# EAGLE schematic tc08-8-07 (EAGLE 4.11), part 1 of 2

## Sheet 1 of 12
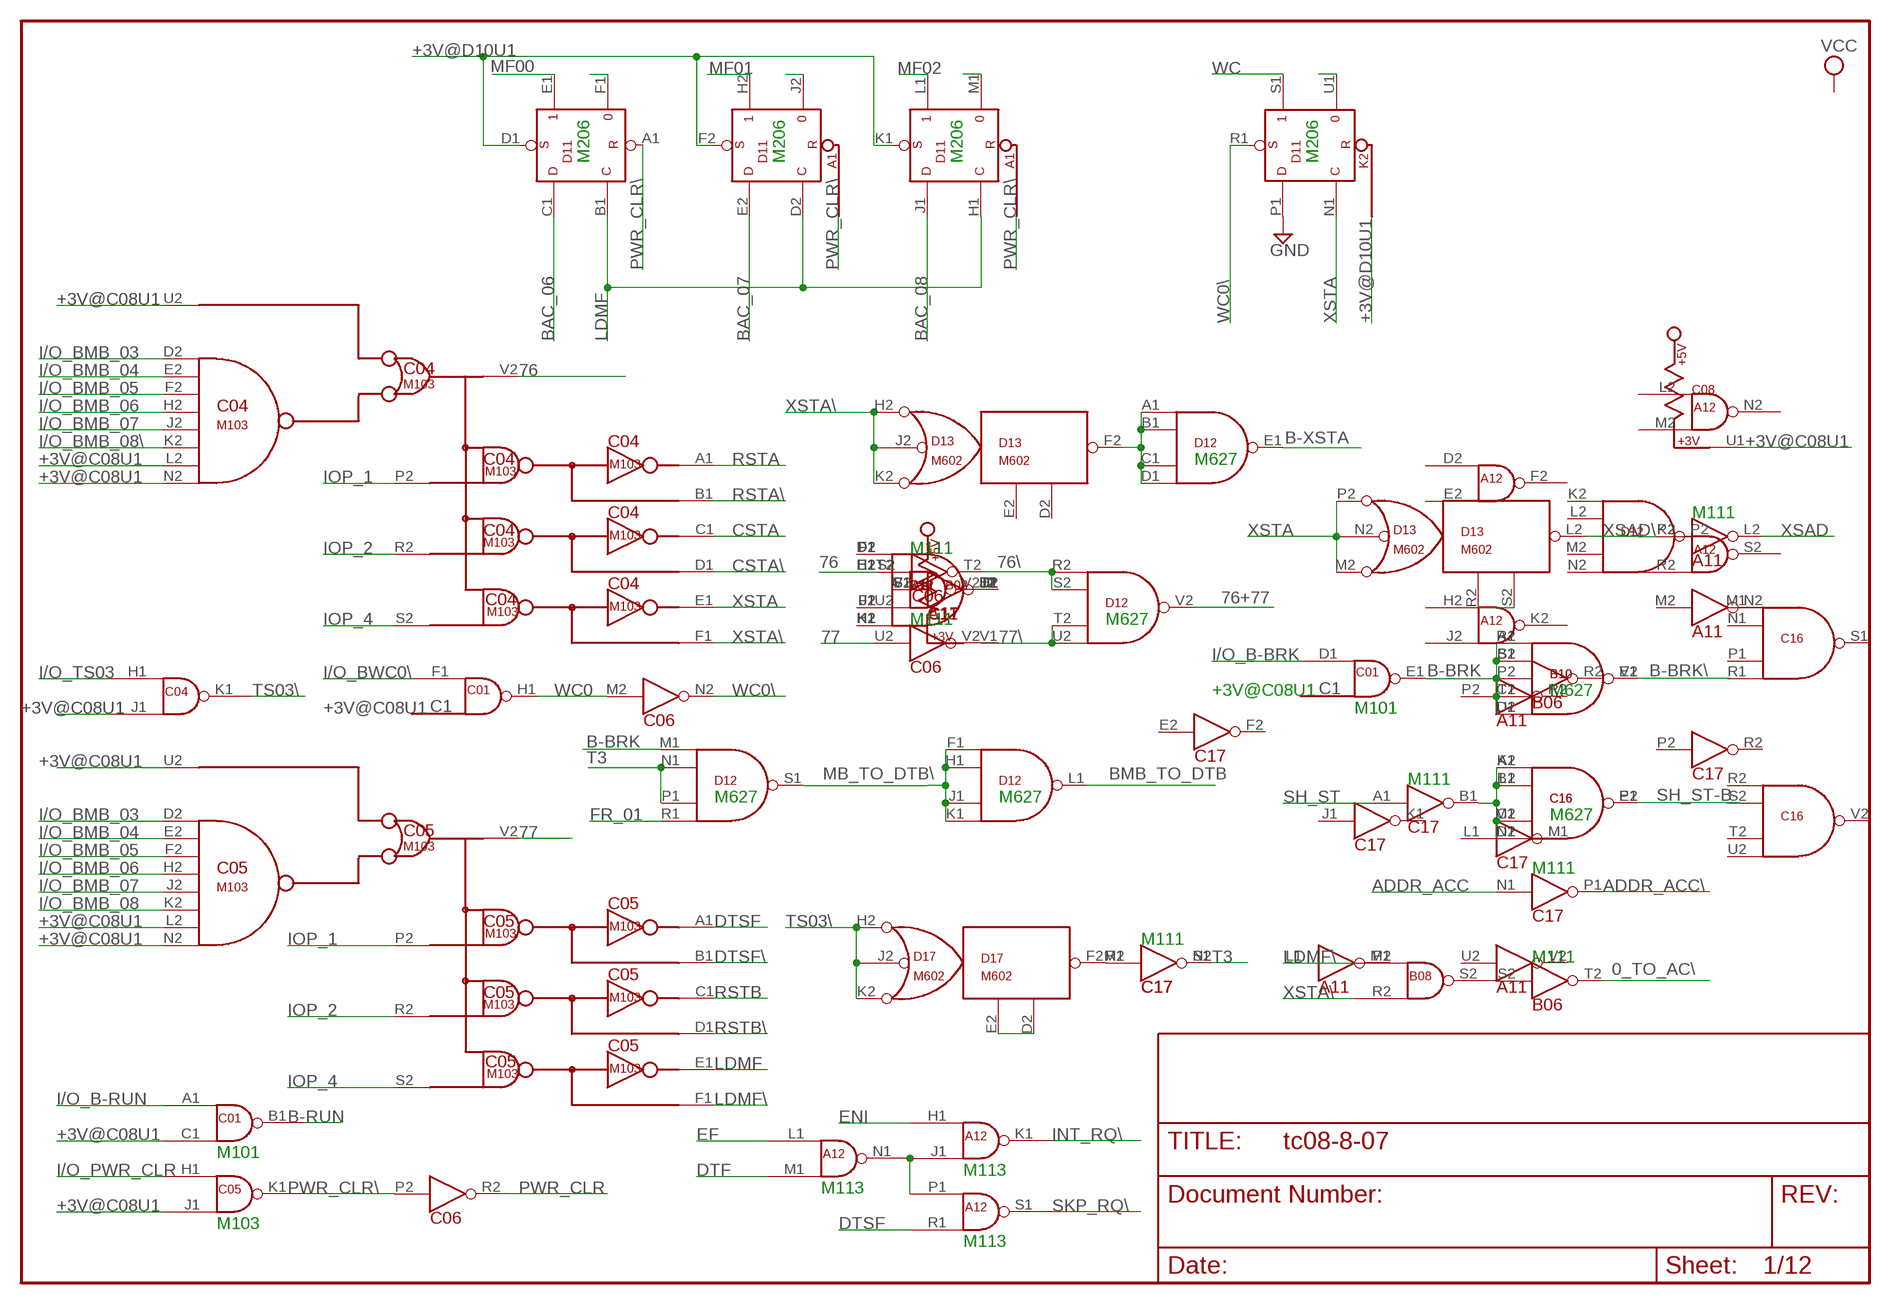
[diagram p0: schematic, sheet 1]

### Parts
A11  M111  [H807]
A12  M113  [H807]
B06  M111  [H807]
B08  M113  [H807]
B10  M627  [H807]
C01  M101  [H807]
C04  M103  [H807]
C05  M103  [H807]
C06  M111  [H807]
C08  M121  [H807]
C16  M627  [H807]
C17  M111  [H807]
D11  M206  M206X  [H807]
D12  M627  [H807]
D13  M602  [H807]
D17  M602  [H807]

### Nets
0_TO_AC\: B06.T2(15:OUT) ; also sheet 11
76: C04.V2 C06.S2(15:IN)
76+77: D12.V2(OUT) ; also sheet 11
76\: C06.T2(15:OUT) D12.R2(IN1) D12.S2(IN2)
77: C05.V2 C06.U2(16:IN)
77\: C06.V2(16:OUT) D12.T2(IN3) D12.U2(IN4)
+3V@C08U1: C01.C1(IN2) C04.J1(IN2) C04.L2 C04.N2 C04.U2 C05.J1(IN2) C05.L2 C05.N2 C05.U2 C08.U1 ; also sheet 11
+3V@D10U1: D11.D1(A1:S) D11.F2(A1B:S) D11.K1(A1C:S) ; also sheet 3,4
ADDR_ACC: C17.N1(10:IN) ; also sheet 11
ADDR_ACC\: C17.P1(10:OUT) ; also sheet 4
B-BRK: B10.R2(IN1) B10.S2(IN2) B10.T2(IN3) B10.U2(IN4) C01.E1(OUT) D12.M1(IN1)
B-BRK\: B10.V2(OUT) ; also sheet 11
B-RUN: C01.B1(OUT) ; also sheet 2
B-XSTA: D12.E1(OUT) ; also sheet 4,6
BAC_06: D11.C1(A1:D) ; also sheet 2,10
BAC_07: D11.E2(A1B:D) ; also sheet 2,10
BAC_08: D11.J1(A1C:D) ; also sheet 2,10
BMB_TO_DTB: D12.L1(OUT) ; also sheet 8
CSTA: C04.C1 ; also sheet 6
CSTA\: C04.D1 ; also sheet 2
DTF: A12.M1(IN2) ; also sheet 4,6,12
DTSF: A12.R1(IN2) C05.A1
DTSF\: C05.B1
EF: A12.L1(IN1) ; also sheet 6,12
ENI: A12.H1(IN1) ; also sheet 2,12
FR_01: D12.R1(IN4) ; also sheet 2,5,6,12
GND [Power]: D11.P1(K2B:D) ; also sheet 2,4,10,11,12
I/O_B-BRK: C01.D1(IN) ; also sheet 12
I/O_B-RUN: C01.A1(IN1) ; also sheet 12
I/O_BMB_03: C04.D2 C05.D2 ; also sheet 11,12
I/O_BMB_04: C04.E2 C05.E2 ; also sheet 11,12
I/O_BMB_05: C04.F2 C05.F2 ; also sheet 11,12
I/O_BMB_06: C04.H2 C05.H2 ; also sheet 11,12
I/O_BMB_07: C04.J2 C05.J2 ; also sheet 11,12
I/O_BMB_08: C05.K2 ; also sheet 11,12
I/O_BMB_08\: C04.K2 ; also sheet 12
I/O_BWC0\: C01.F1(IN) ; also sheet 12
I/O_PWR_CLR: C05.H1(IN1) ; also sheet 12
I/O_TS03: C04.H1(IN1) ; also sheet 12
INT_RQ\: A12.K1(OUT) ; also sheet 11
IOP_1: C04.P2 C05.P2 ; also sheet 12
IOP_2: C04.R2 C05.R2 ; also sheet 12
IOP_4: C04.S2 C05.S2 ; also sheet 12
LDMF: C05.E1 D11.B1(A1:C) D11.D2(A1B:C) D11.H1(A1C:C)
LDMF\: B08.P2(IN1) C05.F1
MB_TO_DTB\: D12.F1(IN1) D12.H1(IN2) D12.J1(IN3) D12.K1(IN4) D12.S1(OUT)
MF00: D11.E1 ; also sheet 12
MF00\: D11.F1 ; also sheet 11
MF01: D11.H2 ; also sheet 12
MF01\: D11.J2 ; also sheet 11
MF02: D11.L1 ; also sheet 12
MF02\: D11.M1 ; also sheet 11
N$1: B06.S2(15:IN) B08.S2(OUT)
N$2: C16.K2(IN1) C16.L2(IN2) C16.M2(IN3) C16.N2(IN4) C17.B1(1:OUT)
N$4: D13.R2(E2) D13.S2(D2)
N$6: D12.A1(IN1) D12.B1(IN2) D12.C1(IN3) D12.D1(IN4) D13.F2
N$7: A12.J1(IN2) A12.N1(OUT) A12.P1(IN1)
N$8: C17.R1(12:IN) D17.F2
N$12: D17.D2 D17.E2
PWR_CLR: C06.R2(13:OUT)
PWR_CLR\: C05.K1(OUT) C06.P2(13:IN) D11.A1(A1:R) ; also sheet 2,4,5,6
RSTA: C04.A1
RSTA\: C04.B1 ; also sheet 11
RSTB: C05.C1
RSTB\: C05.D1 ; also sheet 11
SH_ST: C17.A1(1:IN) ; also sheet 7
SH_ST-B: C16.P2(OUT) ; also sheet 7
SKP_RQ\: A12.S1(OUT) ; also sheet 11
T3: C17.S1(12:OUT) D12.N1(IN2) D12.P1(IN3)
TS03\: C04.K1(OUT) D17.H2 D17.J2 D17.K2
WC: D11.S1 ; also sheet 4,5,12
WC0: C01.H1(OUT) C06.M2(11:IN)
WC0\: C06.N2(11:OUT) D11.R1(K2B:S)
WC\: D11.U1 ; also sheet 4
XSAD: A11.L2(9:OUT) ; also sheet 6
XSAD\: A11.K2(9:IN) D13.L2(F2)
XSTA: C04.E1 D11.N1(K2B:C) D13.M2(K2) D13.N2(J2) D13.P2(H2) ; also sheet 2
XSTA\: B08.R2(IN2) C04.F1 D13.H2 D13.J2 D13.K2 ; also sheet 3,6
Unconnected: A12.U1 A12.V1 B06.M2(11:IN) B06.N2(11:OUT) B06.U2(16:IN) B06.V2(16:OUT) B08.U1 B10.K2(IN1) B10.L2(IN2) B10.M2(IN3) B10.N2(IN4) B10.P2(OUT) B10.U1 B10.V1 C01.E2(IN) C01.F2(OUT) C01.H2(IN) C01.J1(IN) C01.J2(OUT) C01.K1(OUT) C01.K2(IN) C01.L1(IN) C01.L2(OUT) C01.M1(OUT) C01.M2(IN) C01.N1(IN) C01.N2(OUT) C01.P1(OUT) C01.P2(IN) C01.R1(IN) C01.R2(OUT) C01.S1(OUT) C01.S2(IN) C01.T2(OUT) C01.U1(OUT) C01.U2(IN) C01.V1(IN) C01.V2(OUT) C04.L1(IN1) C04.M1(IN2) C04.N1(OUT) C04.V1 C05.L1(IN1) C05.M1(IN2) C05.N1(OUT) C05.V1 C08.V1 C16.U1 C16.V1 C17.D1(3:IN) C17.E1(3:OUT) C17.K2(9:IN) C17.L2(9:OUT) C17.U2(16:IN) C17.V2(16:OUT) D12.U1 D12.V1 D13.D2 D13.E2

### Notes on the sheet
- M206 | M206 | M206 | M206
- M627
- M111
- M111
- M111 | M627
- +3V@C08U1 | M627
- M101
- M111
- M627 | M627
- M627
- M111
- M111
- M111
- M101
- M113
- M113
- M103
- M113

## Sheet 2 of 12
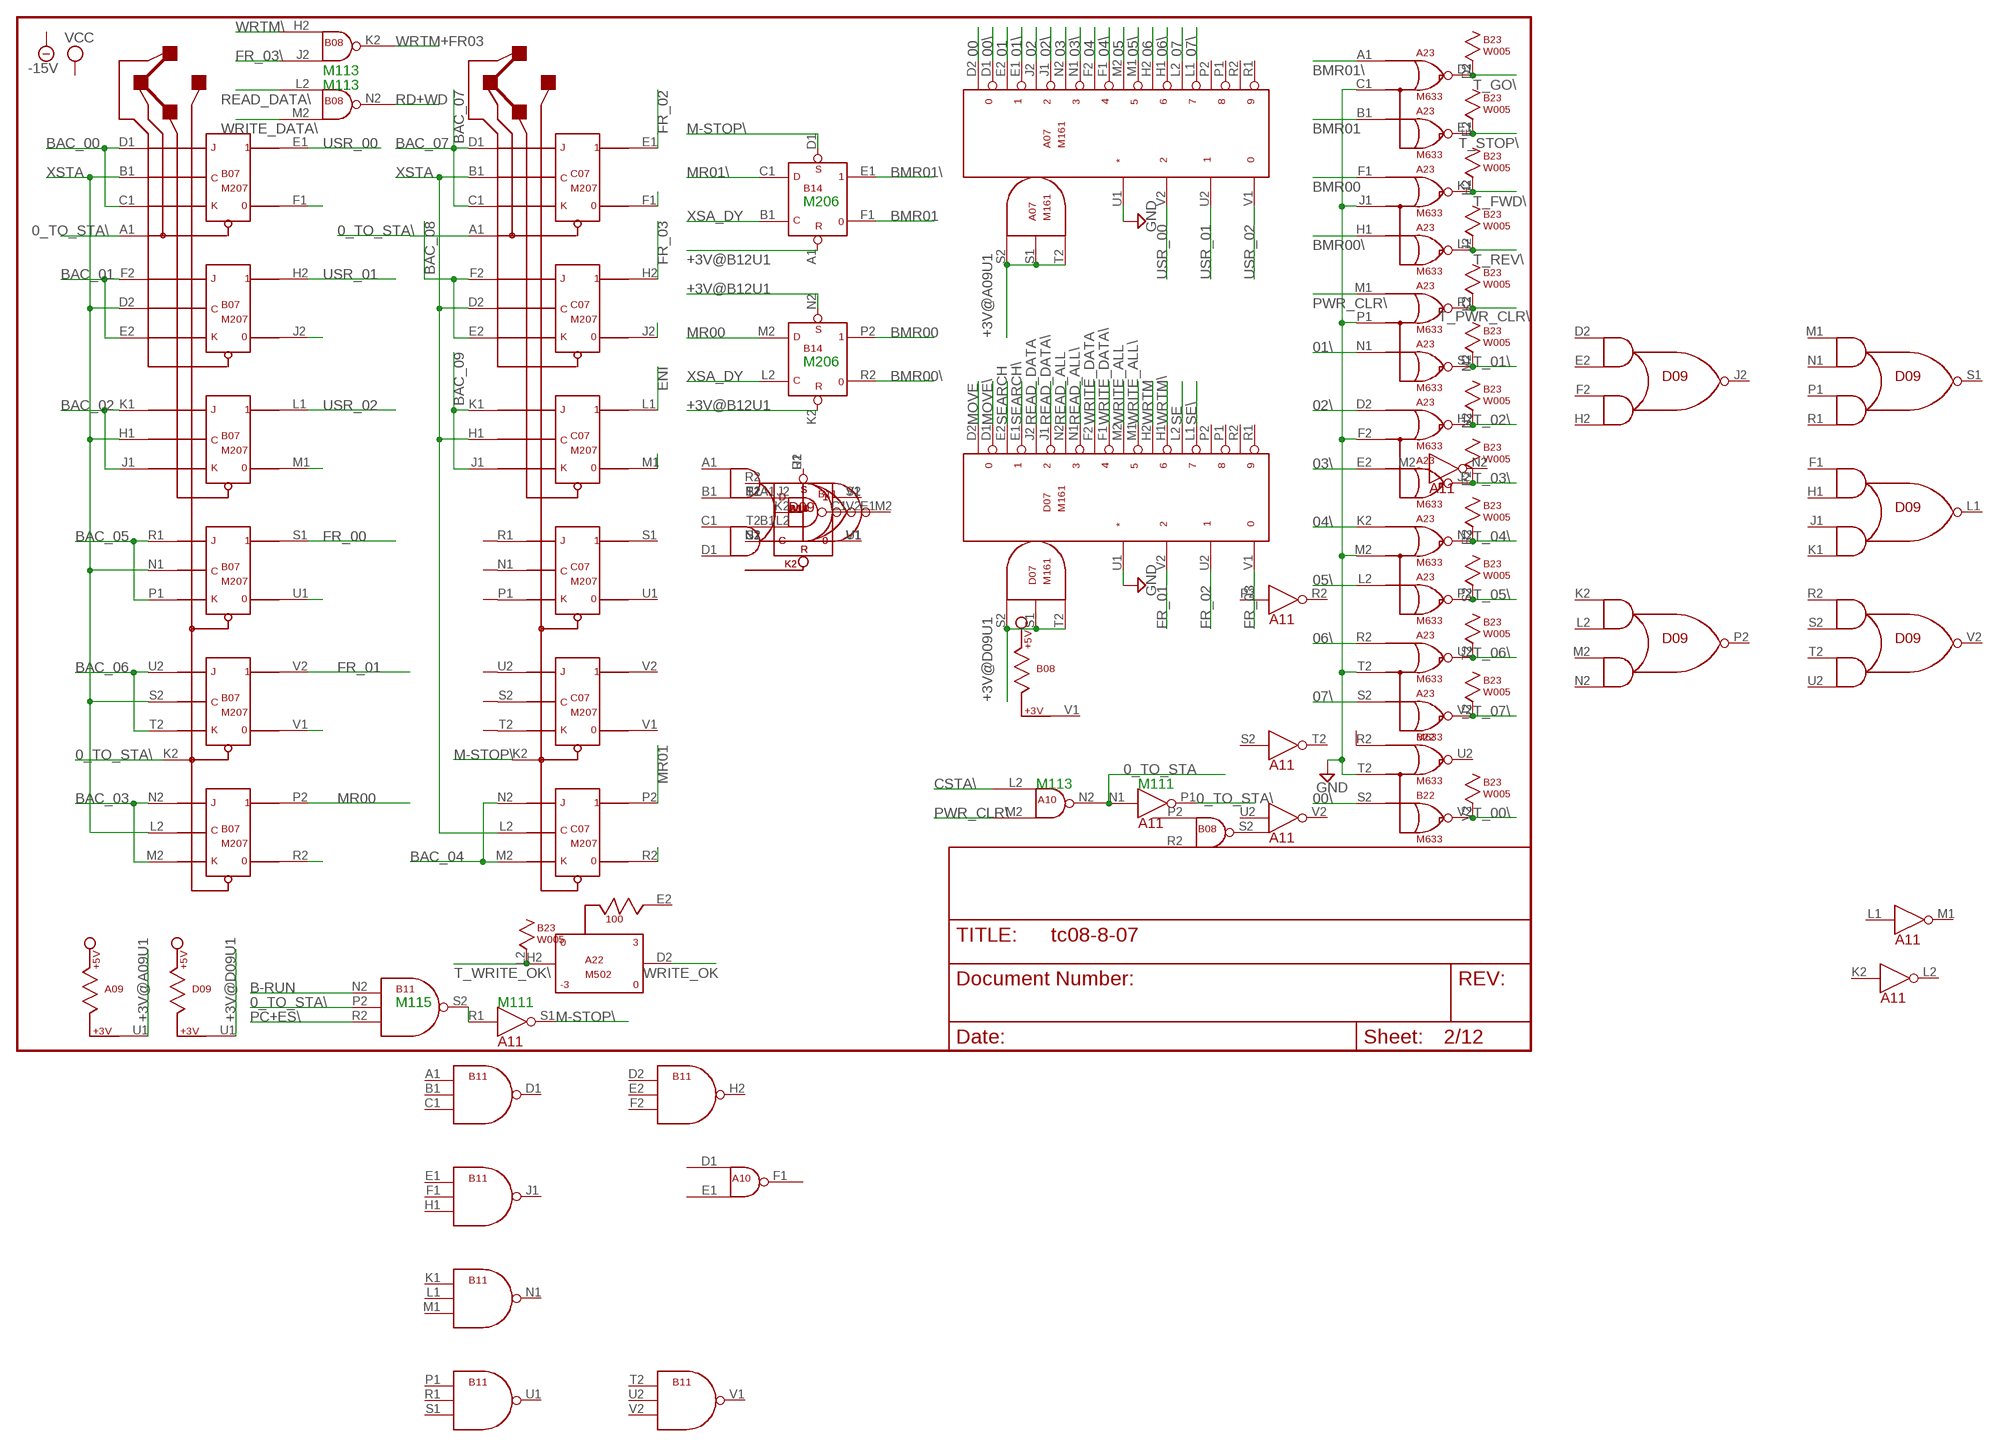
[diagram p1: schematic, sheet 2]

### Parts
A07  M161  [H807]
A09  M117  [H807]
A10  M113  [H807]
A22  M502  [H807]
A23  M633  [H807]
B07  M207  [H807]
B11  M115  [H807]
B14  M206  M206X  [H807]
B22  M633  [H807]
B23  W005  [H807]
C07  M207  [H807]
D07  M161  [H807]
D09  M121  [H807]

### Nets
00: A07.D2(O0)
00\: A07.D1(O0\) B22.S2(B)
0_TO_STA: A10.N2(OUT) A11.N1(10:IN)
0_TO_STA\: A11.P1(10:OUT) B07.A1 B07.K2 B11.P2(IN2) C07.A1
01: A07.E2(O1)
01\: A07.E1(O1\) A23.N1(B)
02: A07.J2(O2)
02\: A07.J1(O2\) A23.D2(A)
03: A07.N2(O3)
03\: A07.N1(O3\) A23.E2(B)
04: A07.F2(O4)
04\: A07.F1(O4\) A23.K2(A)
05: A07.M2(O5)
05\: A07.M1(O5\) A23.L2(B)
06: A07.H2(O6)
06\: A07.H1(O6\) A23.R2(A)
07: A07.L2(O7)
07\: A07.L1(O7\) A23.S2(B)
+3V@A09U1: A07.S1(EN2) A07.S2(EN1) A07.T2(EN3) A09.U1 ; also sheet 4,6
+3V@B12U1: B14.A1(A1:R) B14.K2(K2:R) B14.N2(K2:S) ; also sheet 3,4
+3V@D09U1: D07.S1(EN2) D07.S2(EN1) D07.T2(EN3) D09.U1
B-RUN: B11.N2(IN1) ; also sheet 1
BAC_00: B07.C1 B07.D1 ; also sheet 10
BAC_01: B07.E2 B07.F2 ; also sheet 10
BAC_02: B07.J1 B07.K1 ; also sheet 10
BAC_03: B07.M2 B07.N2 ; also sheet 10
BAC_04: C07.M2 C07.N2 ; also sheet 10
BAC_05: B07.P1 B07.R1 ; also sheet 10
BAC_06: B07.T2 B07.U2 ; also sheet 1,10
BAC_07: C07.C1 C07.D1 ; also sheet 1,10
BAC_08: C07.E2 C07.F2 ; also sheet 1,10
BAC_09: C07.J1 C07.K1 ; also sheet 10
BMR00: A23.F1(A) B14.P2
BMR00\: A23.H1(B) B14.R2
BMR01: A23.B1(B) B14.F1
BMR01\: A23.A1(A) B14.E1
CSTA\: A10.L2(IN1) ; also sheet 1
ENI: C07.L1 ; also sheet 1,12
ENI\: C07.M1 ; also sheet 11
FR_00: B07.S1 ; also sheet 4,12
FR_00\: B07.U1 ; also sheet 4,11
FR_01: B07.V2 D07.V2(IN2) ; also sheet 1,5,6,12
FR_01\: B07.V1 ; also sheet 5,11
FR_02: C07.E1 D07.U2(IN1) ; also sheet 12
FR_02\: C07.F1 ; also sheet 11
FR_03: C07.H2 D07.V1(IN0) ; also sheet 5,12
FR_03\: B08.J2(IN2) C07.J2 ; also sheet 11
GND [Power]: A07.U1(IN*) A23.C1(C) A23.F2(C) A23.J1(C) A23.M2(C) A23.P1(C) A23.T2(C) B22.T2(C) D07.U1(IN*) ; also sheet 1,4,10,11,12
M-STOP\: A11.S1(12:OUT) B14.D1(A1:S) C07.K2 ; also sheet 3
MOVE: D07.D2(O0)
MOVE\: D07.D1(O0\) ; also sheet 6
MR00: B07.P2 B14.M2(K2:D) ; also sheet 12
MR00\: B07.R2 ; also sheet 11
MR01: C07.P2 ; also sheet 3,12
MR01\: B14.C1(A1:D) C07.R2 ; also sheet 11
N$3: A11.R1(12:IN) B11.S2(OUT)
NC: B22.R2(A) C07.N1 C07.P1 C07.R1 C07.S2 C07.T2 C07.U2 ; also sheet 3,10,11,12
PC+ES\: B11.R2(IN3) ; also sheet 6
PWR_CLR\: A10.M2(IN2) A23.M1(A) ; also sheet 1,4,5,6
RD+WD: B08.N2(OUT) ; also sheet 4,6
READ_ALL: D07.N2(O3)
READ_ALL\: D07.N1(O3\) ; also sheet 4
READ_DATA: D07.J2(O2) ; also sheet 4,6
READ_DATA\: B08.L2(IN1) D07.J1(O2\) ; also sheet 5
SE: D07.L2(O7)
SE\: D07.L1(O7\) ; also sheet 6
SEARCH: D07.E2(O1) ; also sheet 4
SEARCH\: D07.E1(O1\) ; also sheet 5,11
T_00\: B22.V2(E) B23.V2 ; also sheet 12
T_01\: A23.S1(E) B23.M2 ; also sheet 12
T_02\: A23.H2(D) B23.N2 ; also sheet 12
T_03\: A23.J2(E) B23.P2 ; also sheet 12
T_04\: A23.N2(D) B23.R2 ; also sheet 12
T_05\: A23.P2(E) B23.S2 ; also sheet 12
T_06\: A23.U2(D) B23.T2 ; also sheet 12
T_07\: A23.V2(E) B23.U2 ; also sheet 12
T_FWD\: A23.K1(D) B23.H2 ; also sheet 12
T_GO\: A23.D1(D) B23.D2 ; also sheet 12
T_PWR_CLR\: A23.R1(D) B23.K2 ; also sheet 12
T_REV\: A23.L1(E) B23.J2 ; also sheet 12
T_STOP\: A23.E1(E) B23.E2 ; also sheet 12
T_WRITE_OK\: A22.H2 B23.L2 ; also sheet 12
USR_00: A07.V2(IN2) B07.E1 ; also sheet 12
USR_00\: B07.F1 ; also sheet 11
USR_01: A07.U2(IN1) B07.H2 ; also sheet 12
USR_01\: B07.J2 ; also sheet 11
USR_02: A07.V1(IN0) B07.L1 ; also sheet 12
USR_02\: B07.M1 ; also sheet 11
WRITE_ALL: D07.M2(O5) ; also sheet 4,5
WRITE_ALL\: D07.M1(O5\)
WRITE_DATA: D07.F2(O4) ; also sheet 4,5,9
WRITE_DATA\: B08.M2(IN2) D07.F1(O4\)
WRITE_OK: A22.D2 ; also sheet 5,6
WRTM: D07.H2(O6) ; also sheet 3,5,6
WRTM+FR03: B08.K2(OUT) ; also sheet 4
WRTM\: B08.H2(IN1) D07.H1(O6\) ; also sheet 6
XSA_DY: B14.B1(A1:C) B14.L2(K2:C) ; also sheet 6
XSTA: B07.B1 B07.D2 B07.H1 B07.L2 B07.N1 B07.S2 C07.B1 C07.D2 C07.H1 C07.L2 ; also sheet 1
Unconnected: A07.P1(O8\) A07.P2(O8) A07.R1(O9\) A07.R2(O9) A09.V1 A10.U1 A10.V1 A22.E2 A22.P2(E2) A22.R2(D2) A22.U2(H2) B14.D2(A1B:C) B14.E2(A1B:D) B14.F2(A1B:S) B14.H1(A1C:C) B14.H2 B14.J1(A1C:D) B14.J2 B14.K1(A1C:S) B14.L1 B14.M1 B22.A1(A) B22.B1(B) B22.C1(C) B22.D1(D) B22.D2(A) B22.E1(E) B22.E2(B) B22.F1(A) B22.F2(C) B22.H1(B) B22.H2(D) B22.J1(C) B22.J2(E) B22.K1(D) B22.K2(A) B22.L1(E) B22.L2(B) B22.M1(A) B22.M2(C) B22.N1(B) B22.N2(D) B22.P1(C) B22.P2(E) B22.R1(D) B22.S1(E) B22.U2(D) B23.F2 C07.S1 C07.U1 C07.V1 C07.V2 D07.P1(O8\) D07.P2(O8) D07.R1(O9\) D07.R2(O9) D09.V1

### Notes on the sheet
- M113
- M113
- M206
- M206
- M113 | M111
- M115 | M111

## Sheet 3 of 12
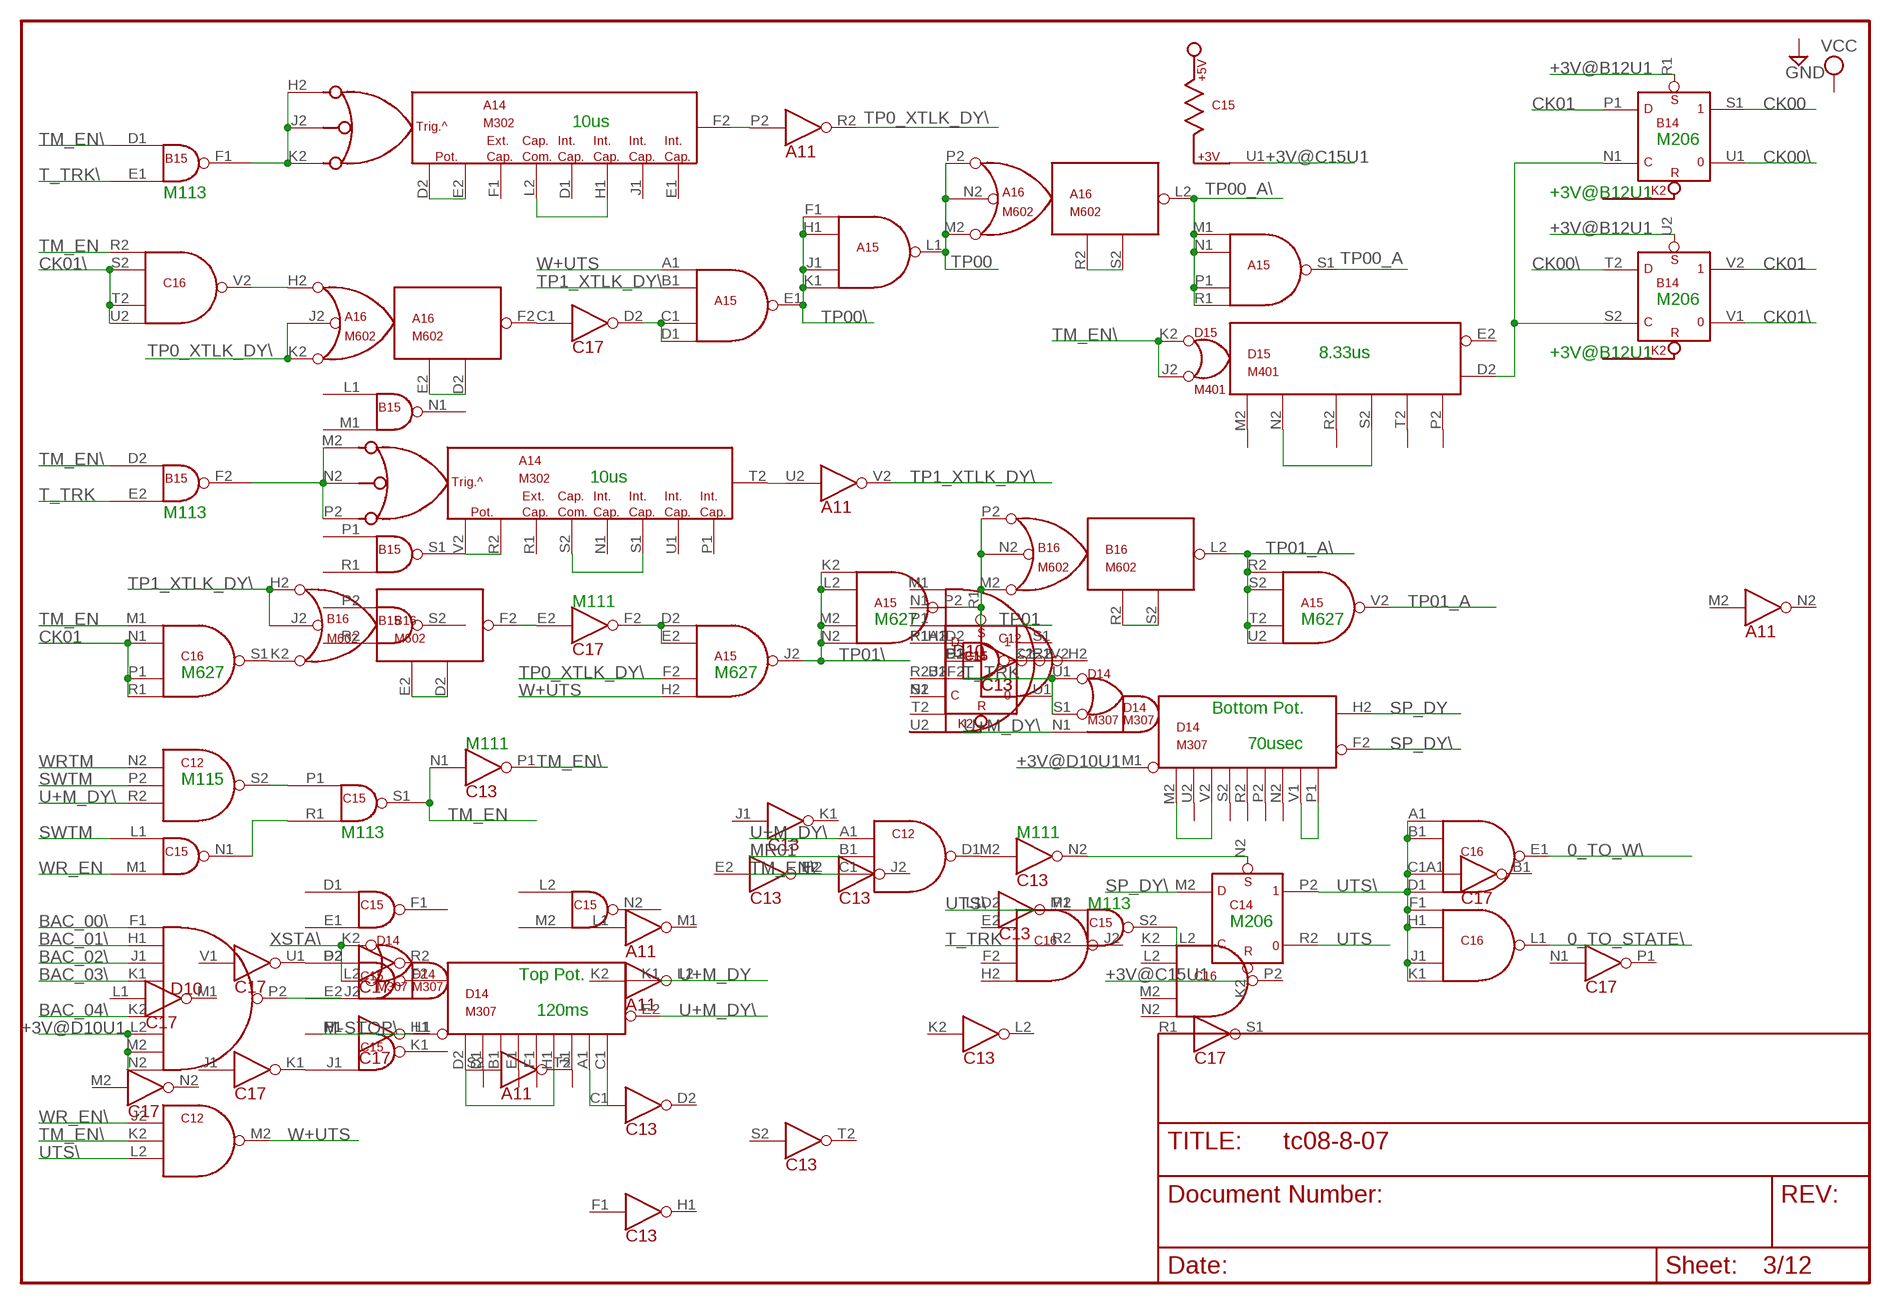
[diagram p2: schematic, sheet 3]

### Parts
A14  M302  [H807]
A15  M627  [H807]
A16  M602  [H807]
B15  M113  [H807]
B16  M602  [H807]
C12  M115  [H807]
C13  M111  [H807]
C14  M206  M206X  [H807]
C15  M113  [H807]
D10  M119  [H807]
D14  M307  [H807]
D15  M401  [H807]

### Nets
0_TO_STATE\: C16.L1(OUT) ; also sheet 7
0_TO_W\: C16.E1(OUT) ; also sheet 7
+3V@B12U1: B14.R1(K2B:S) B14.U2(K2C:S) ; also sheet 2,4
+3V@C15U1: C14.K2(K2:R) C15.U1 ; also sheet 5,8
+3V@D10U1: D10.L2(IN6) D10.M2(IN7) D10.N2(IN8) D14.M1 ; also sheet 1,4
BAC_00\: D10.F1(IN1) ; also sheet 10,11
BAC_01\: D10.H1(IN2) ; also sheet 10,11
BAC_02\: D10.J1(IN3) ; also sheet 10,11
BAC_03\: D10.K1(IN4) ; also sheet 10,11
BAC_04\: D10.K2(IN5) ; also sheet 10,11
CK00: B14.S1 ; also sheet 10
CK00\: B14.T2(K2C:D) B14.U1 ; also sheet 10
CK01: B14.P1(K2B:D) B14.V2 C16.N1(IN2) C16.P1(IN3) C16.R1(IN4)
CK01\: B14.V1 C16.S2(IN2) C16.T2(IN3) C16.U2(IN4)
M-STOP\: D14.L1(M1) ; also sheet 2
MR01: C12.B1(IN2) ; also sheet 2,12
N$5: A16.H2 C16.V2(OUT)
N$13: A14.H2 A14.J2 A14.K2 B15.F1(OUT)
N$14: A16.D2 A16.E2
N$15: A16.F2 C17.C1(2:IN)
N$16: A15.C1(IN3) A15.D1(IN4) C17.D2(2:OUT)
N$17: B14.N1(K2B:C) B14.S2(K2C:C) D15.D2
N$18: A14.M2(H2) A14.N2(J2) A14.P2(K2) B15.F2(OUT)
N$19: A14.H1 A14.L2
N$20: A16.R2(E2) A16.S2(D2)
N$21: A14.D2 A14.E2
N$22: A11.U2(16:IN) A14.T2(F2)
N$23: A11.P2(13:IN) A14.F2
N$24: B16.K2 C16.S1(OUT)
N$25: A14.R2(E2) A14.V2(D2)
N$26: A14.S1(H1) A14.S2(L2)
N$27: D15.N2 D15.S2
N$29: B16.D2 B16.E2
N$30: B16.F2 C17.E2(5:IN)
N$31: A15.D2(IN1) A15.E2(IN2) C17.F2(5:OUT)
N$37: B16.R2(E2) B16.S2(D2)
N$40: D14.M2 D14.V2
N$41: D14.P1 D14.V1
N$50: C12.S2(OUT) C15.P1(IN1)
N$53: C15.N1(OUT) C15.R1(IN2)
N$67: D10.P2(OUT) D14.J2(N1)
N$68: D14.D2(M2) D14.H1(P2)
N$69: D14.A1(V1) D14.C1(P1)
N$76: C14.L2(K2:C) C15.S2(OUT)
N$79: C13.N2(11:OUT) C14.N2(K2:S)
N$81: C12.D1(OUT) C13.M2(11:IN)
NC: D14.B1(V2) D14.D1(U2) D14.E1(S2) D14.F1(R2) D14.J1(N2) D14.N2 D14.P2 D14.R2 D14.S2 D14.U2 D15.M2 D15.P2 D15.R2 D15.T2 ; also sheet 2,10,11,12
SP_DY: D14.H2
SP_DY\: C14.M2(K2:D) D14.F2
SWTM: C12.P2(IN2) C15.L1(IN1) ; also sheet 5,6,12
T_TRK: B15.E2(IN2) C15.R2(IN2) D14.S1 D14.U1 ; also sheet 10
T_TRK\: B15.E1(IN2) ; also sheet 10
TM_EN: C13.N1(10:IN) C15.S1(OUT) C16.M1(IN1) C16.R2(IN1) ; also sheet 10
TM_EN\: B15.D1(IN1) B15.D2(IN1) C12.C1(IN3) C12.K2(IN2) C13.P1(10:OUT) D15.J2 D15.K2
TP00: A15.L1(OUT) A16.M2(K2) A16.N2(J2) A16.P2(H2) ; also sheet 4,5,6
TP00\: A15.E1(OUT) A15.F1(IN1) A15.H1(IN2) A15.J1(IN3) A15.K1(IN4) ; also sheet 4,7
TP00_A: A15.S1(OUT) ; also sheet 5,9
TP00_A\: A15.M1(IN1) A15.N1(IN2) A15.P1(IN3) A15.R1(IN4) A16.L2(F2)
TP0_XTLK_DY\: A11.R2(13:OUT) A15.F2(IN3) A16.J2 A16.K2
TP01: A15.P2(OUT) B16.M2(K2) B16.N2(J2) B16.P2(H2) ; also sheet 5,7,9
TP01\: A15.J2(OUT) A15.K2(IN1) A15.L2(IN2) A15.M2(IN3) A15.N2(IN4) ; also sheet 4
TP01_A: A15.V2(OUT) ; also sheet 4,9
TP01_A\: A15.R2(IN1) A15.S2(IN2) A15.T2(IN3) A15.U2(IN4) B16.L2(F2)
TP1_XTLK_DY\: A11.V2(16:OUT) A15.B1(IN2) B16.H2 B16.J2
U+M_DY: D14.K1(H2)
U+M_DY\: C12.A1(IN1) C12.R2(IN3) D14.E2(F2) D14.N1
UTS: C14.R2 ; also sheet 5,12
UTS\: C12.L2(IN3) C14.P2 C15.P2(IN1) C16.A1(IN1) C16.B1(IN2) C16.C1(IN3) C16.D1(IN4) C16.F1(IN1) C16.H1(IN2) C16.J1(IN3) C16.K1(IN4)
W+UTS: A15.A1(IN1) A15.H2(IN4) C12.M2(OUT)
WR_EN: C15.M1(IN2) ; also sheet 5,9,10,12
WR_EN\: C12.J2(IN1) ; also sheet 5,9
WRTM: C12.N2(IN1) ; also sheet 2,5,6
XSTA\: D14.K2(U1) D14.L2(S1) ; also sheet 1,6
Unconnected: A14.D1 A14.E1 A14.F1 A14.J1 A14.N1(D1) A14.P1(E1) A14.R1(F1) A14.U1(J1) A15.U1 A15.V1 B15.A1(IN1) B15.B1(IN2) B15.C1(OUT) B15.H2(IN1) B15.J2(IN2) B15.K2(OUT) B15.L2(IN1) B15.M2(IN2) B15.N2(OUT) B15.T2(IN1) B15.U1 B15.U2(IN2) B15.V1 B15.V2(OUT) C13.U2(16:IN) C13.V2(16:OUT) C14.S2(K2C:C) C14.T2(K2C:D) C14.U2(K2C:S) C14.V1 C14.V2 C15.T2(IN1) C15.U2(IN2) C15.V1 C15.V2(OUT) D10.V1 D14.R1 D15.E2

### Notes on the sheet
- 10us
- M206
- M113 | +3V@B12U1
- M206
- 8.33us | +3V@B12U1
- 10us
- M113
- M111
- M627 | M627
- M627 | M627
- Bottom Pot.
- M111 | 70usec
- M115
- M113 | M111
- M113
- M206
- Top Pot.
- 120ms

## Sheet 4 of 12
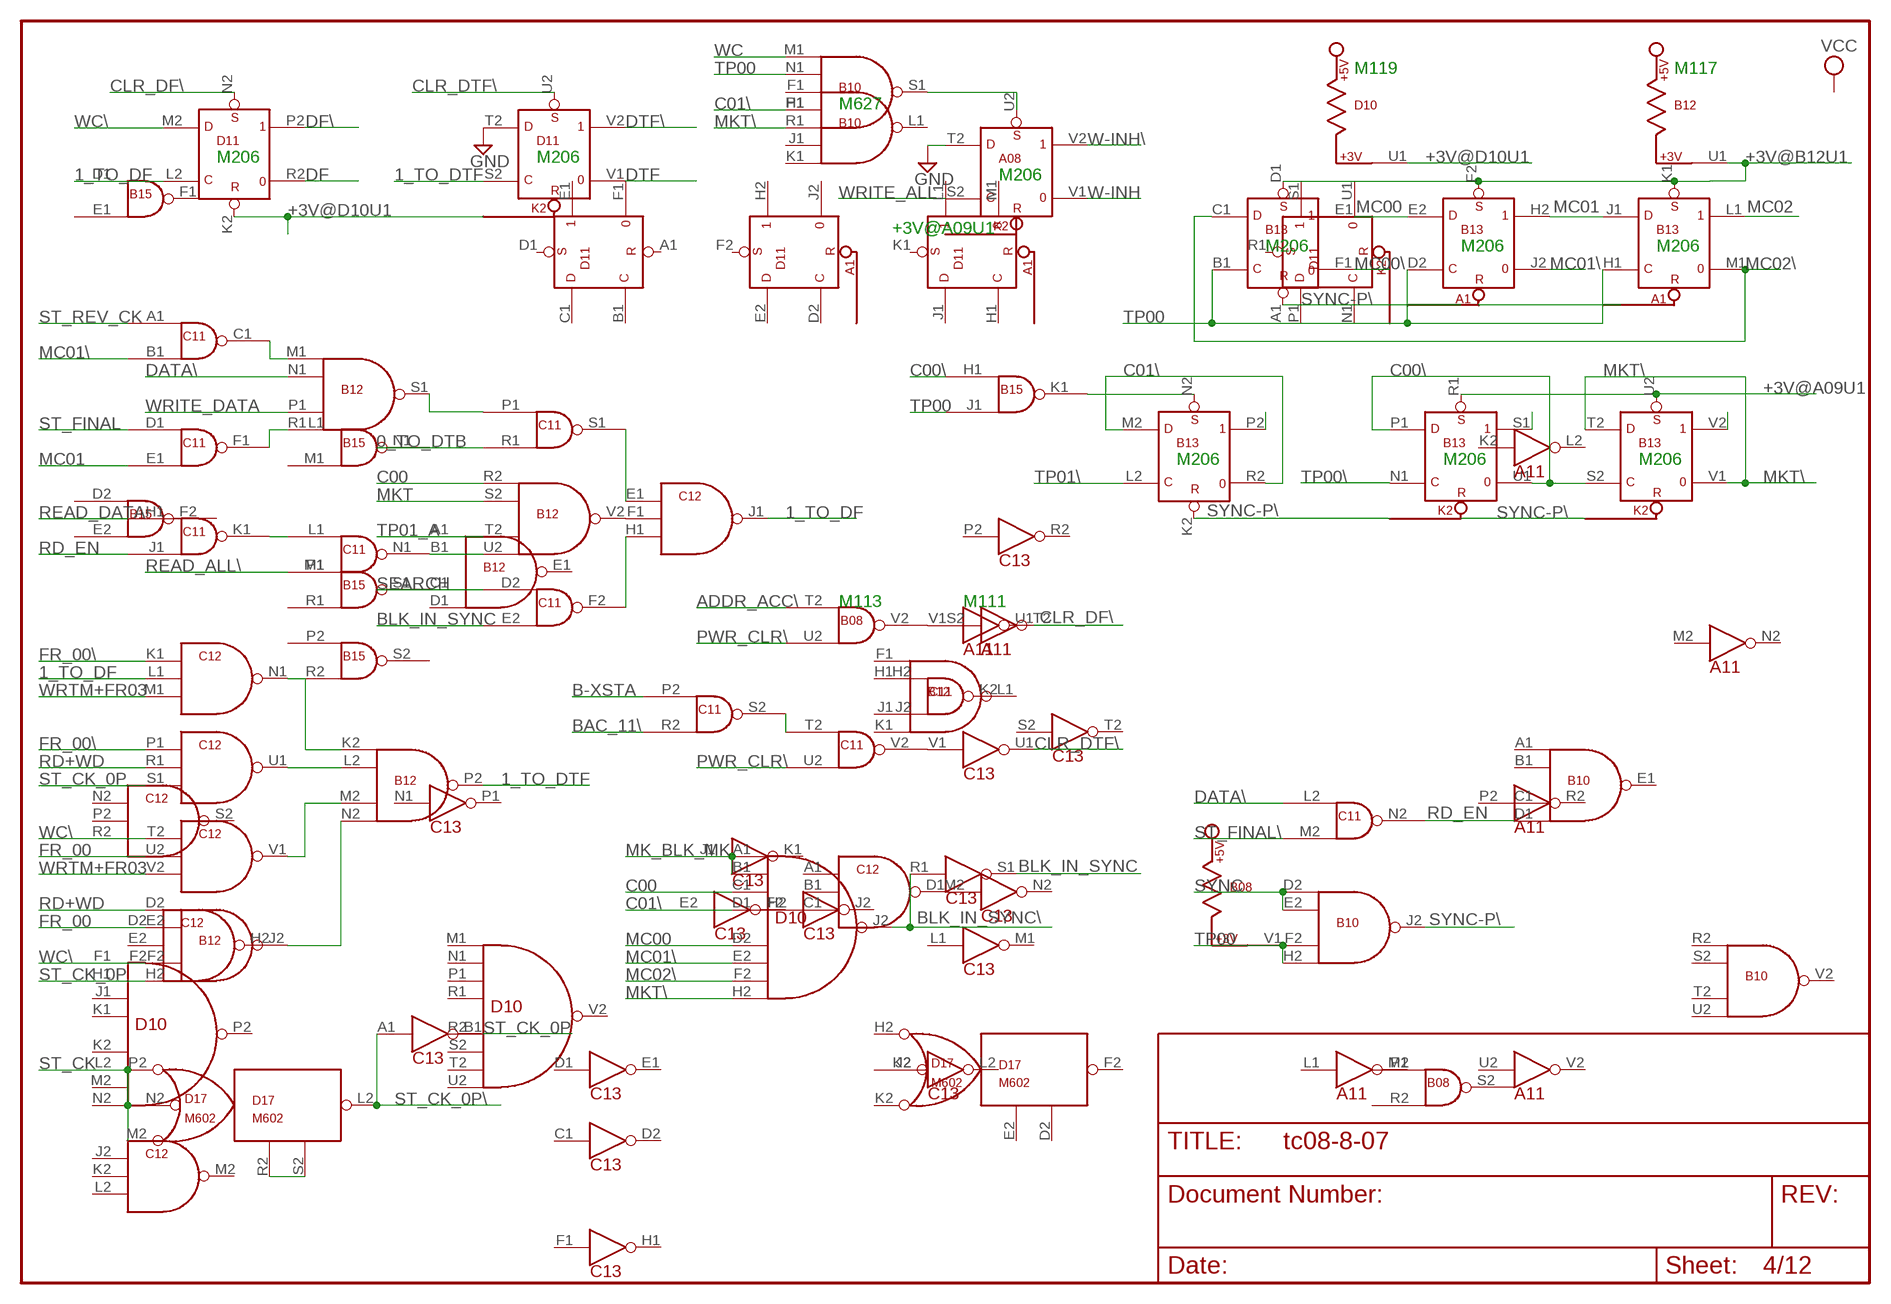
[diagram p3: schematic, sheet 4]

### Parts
A08  M206  M206X  [H807]
B12  M117  [H807]
B13  M206  M206X  [H807]
C11  M113  [H807]

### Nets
0_TO_DTB: C11.R1(IN2) ; also sheet 5
1_TO_DF: C12.J1(OUT) C12.L1(IN2) D11.L2(K2:C) ; also sheet 6
1_TO_DTF: B12.P2(OUT) D11.S2(K2C:C)
+3V@A09U1: B13.R1(K2B:S) B13.U2(K2C:S) ; also sheet 2,6
+3V@B12U1: B12.U1 B13.D1(A1:S) B13.F2(A1B:S) B13.K1(A1C:S) ; also sheet 2,3
+3V@D10U1: D10.U1 D11.K2(K2:R) ; also sheet 1,3
ADDR_ACC\: B08.T2(IN1) ; also sheet 1
B-XSTA: C11.P2(IN1) ; also sheet 1,6
BAC_11\: C11.R2(IN2) ; also sheet 10,11
BLK_IN_SYNC: C11.E2(IN2) C13.S1(12:OUT) ; also sheet 7
BLK_IN_SYNC\: C13.R1(12:IN) D10.J2(OUT) ; also sheet 5
C00: B12.R2(IN1) B13.S1 D10.C1(IN3) ; also sheet 5,9,12
C00\: B13.P1(K2B:D) B13.S2(K2C:C) B13.U1 B15.H1(IN1) ; also sheet 5,9
C01: B13.P2 ; also sheet 5,12
C01\: B10.P1(IN3) B13.M2(K2:D) B13.R2 D10.D1(IN4) ; also sheet 5,9
CLR_DF\: A11.U1(14:OUT) D11.N2(K2:S)
CLR_DTF\: C13.U1(14:OUT) D11.U2(K2C:S)
DATA\: B12.N1(IN2) C11.L2(IN1) ; also sheet 5
DF: D11.R2 ; also sheet 6,12
DF\: D11.P2 ; also sheet 5,11
DTF: D11.V1 ; also sheet 1,6,12
DTF\: D11.V2 ; also sheet 5,11
FR_00: B12.E2(IN2) C12.U2(IN2) ; also sheet 2,12
FR_00\: C12.K1(IN1) C12.P1(IN1) ; also sheet 2,11
GND [Power]: A08.T2(K2C:D) D11.T2(K2C:D) ; also sheet 1,2,10,11,12
MC00: B13.E1 B13.E2(A1B:D) D10.D2(IN5) ; also sheet 12
MC00\: B13.F1 ; also sheet 5,6
MC01: B13.H2 B13.J1(A1C:D) C11.E1(IN2) ; also sheet 6,12
MC01\: B13.J2 C11.B1(IN2) D10.E2(IN6) ; also sheet 5
MC02: B13.L1 ; also sheet 5,9,12
MC02\: B13.C1(A1:D) B13.M1 D10.F2(IN7)
MK_BLK_MK: D10.A1(IN1) D10.B1(IN2) ; also sheet 7
MKT: B12.S2(IN2) B13.V2 ; also sheet 5,9,12
MKT\: B10.R1(IN4) B13.T2(K2C:D) B13.V1 D10.H2(IN8) ; also sheet 5
N$10: B12.M1(IN1) C11.C1(OUT)
N$11: B12.R1(IN4) C11.F1(OUT)
N$28: B12.L2(IN2) C12.U1(OUT)
N$33: A08.U2(K2C:S) B10.S1(OUT)
N$42: C11.K1(OUT) C11.L1(IN1)
N$44: B12.U2(IN4) C11.N1(OUT)
N$48: B12.S1(OUT) C11.P1(IN1)
N$51: B12.V2(OUT) C12.F1(IN2)
N$52: C11.S1(OUT) C12.E1(IN1)
N$54: C11.F2(OUT) C12.H1(IN3)
N$58: A11.V1(14:IN) B08.V2(OUT)
N$59: C11.V2(OUT) C13.V1(14:IN)
N$60: B12.K2(IN1) C12.N1(OUT)
N$61: B12.M2(IN3) C12.V1(OUT)
N$62: B12.J2(OUT) B12.N2(IN4)
N$63: B13.N2(K2:S) B15.K1(OUT)
N$65: C11.S2(OUT) C11.T2(IN1)
N$88: D17.R2(E2) D17.S2(D2)
PWR_CLR\: B08.U2(IN2) C11.U2(IN2) ; also sheet 1,2,5,6
RD+WD: B12.D2(IN1) C12.R1(IN2) ; also sheet 2,6
RD_EN: C11.J1(IN2) C11.N2(OUT)
READ_ALL\: C11.M1(IN2) ; also sheet 2
READ_DATA: C11.H1(IN1) ; also sheet 2,6
SEARCH: C11.D2(IN1) ; also sheet 2
ST_CK: D17.M2(K2) D17.N2(J2) D17.P2(H2) ; also sheet 5,6,7,12
ST_CK_0P: B12.H2(IN4) C12.S1(IN3) C13.B1(1:OUT)
ST_CK_0P\: C13.A1(1:IN) D17.L2(F2)
ST_FINAL: C11.D1(IN1) ; also sheet 5,7,9,12
ST_FINAL\: C11.M2(IN2) ; also sheet 5
ST_REV_CK: C11.A1(IN1) ; also sheet 5,7,9,12
SYNC: B10.D2(IN1) B10.E2(IN2) ; also sheet 7
SYNC-P\: B10.J2(OUT) B13.A1(A1:R) B13.K2(K2:R)
TP00: B10.F2(IN3) B10.H2(IN4) B10.N1(IN2) B13.B1(A1:C) B13.D2(A1B:C) B13.H1(A1C:C) B15.J1(IN2) ; also sheet 3,5,6
TP00\: B13.N1(K2B:C) ; also sheet 3,7
TP01\: B13.L2(K2:C) ; also sheet 3
TP01_A: B12.T2(IN3) ; also sheet 3,9
W-INH: A08.V1
W-INH\: A08.V2 ; also sheet 5
WC: B10.M1(IN1) ; also sheet 1,5,12
WC\: B12.F2(IN3) C12.T2(IN1) D11.M2(K2:D) ; also sheet 1
WRITE_ALL: A08.S2(K2C:C) ; also sheet 2,5
WRITE_DATA: B12.P1(IN3) ; also sheet 2,5,9
WRTM+FR03: C12.M1(IN3) C12.V2(IN3) ; also sheet 2
Unconnected: B12.V1 C11.U1 C11.V1

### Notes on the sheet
- M119 | M117
- M627
- M206 | M206
- M206
- +3V@A09U1
- M206 | M206 | M206
- M206 | M206 | M206
- M113 | M111

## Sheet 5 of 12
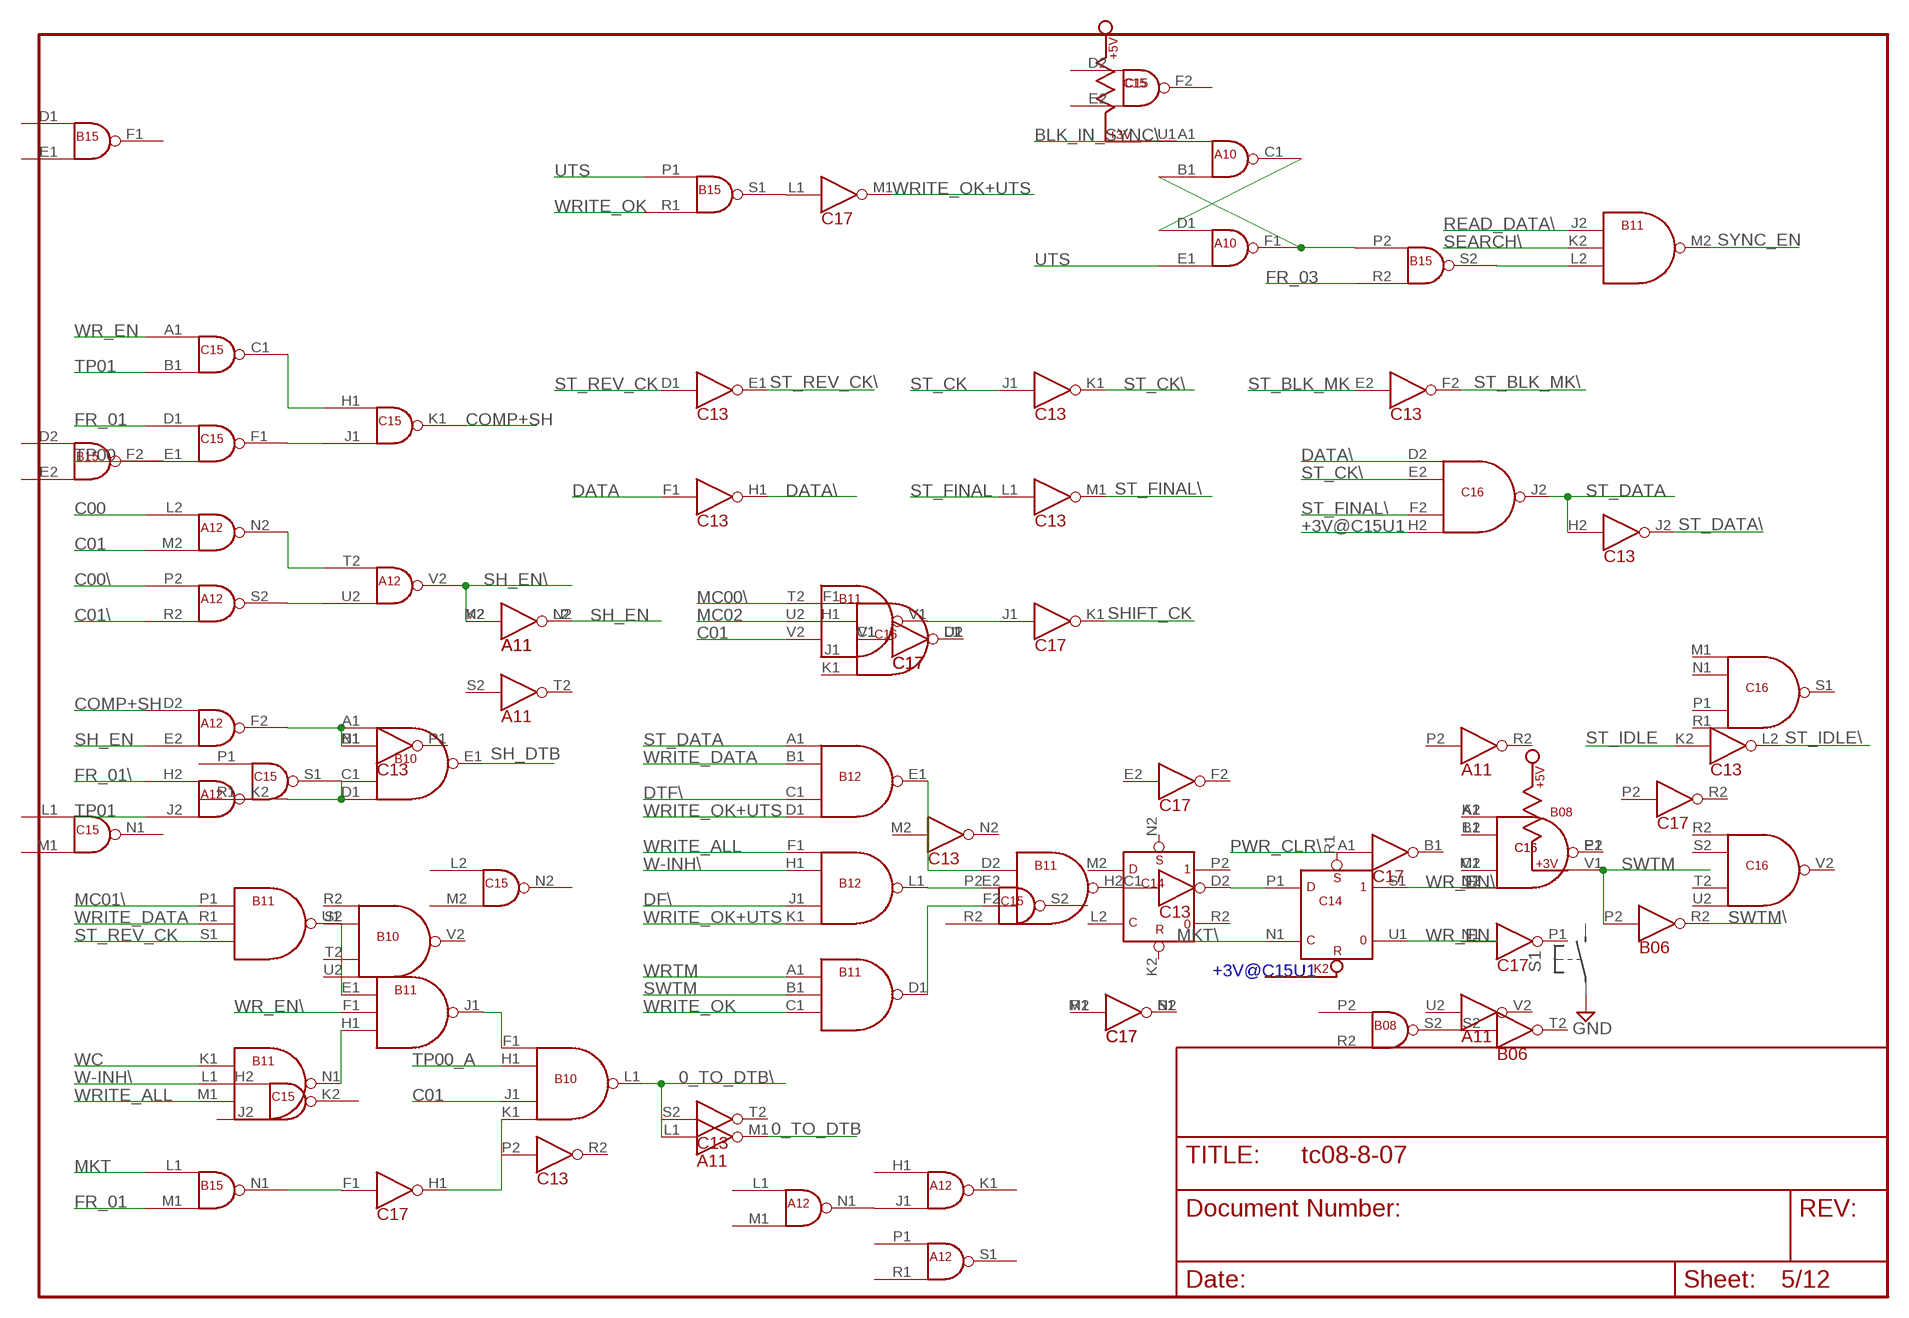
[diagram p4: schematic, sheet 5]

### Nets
0_TO_DTB: A11.M1(8:OUT) ; also sheet 4
0_TO_DTB\: A11.L1(8:IN) B10.L1(OUT) ; also sheet 8
+3V@C15U1: C16.H2(IN4) ; also sheet 3,8
BLK_IN_SYNC\: A10.A1(IN1) ; also sheet 4
C00: A12.L2(IN1) ; also sheet 4,9,12
C00\: A12.P2(IN1) ; also sheet 4,9
C01: A12.M2(IN2) B10.J1(IN3) B11.V2(IN3) ; also sheet 4,12
C01\: A12.R2(IN2) ; also sheet 4,9
COMP+SH: A12.D2(IN1) C15.K1(OUT) ; also sheet 8
DATA: C13.F1(4:IN) ; also sheet 7,12
DATA\: C13.H1(4:OUT) C16.D2(IN1) ; also sheet 4
DF\: B12.J1(IN3) ; also sheet 4,11
DTF\: B12.C1(IN3) ; also sheet 4,11
FR_01: B15.M1(IN2) C15.D1(IN1) ; also sheet 1,2,6,12
FR_01\: A12.H2(IN1) ; also sheet 2,11
FR_03: B15.R2(IN2) ; also sheet 2,12
MC00\: B11.T2(IN1) ; also sheet 4,6
MC01\: B11.P1(IN1) ; also sheet 4
MC02: B11.U2(IN2) ; also sheet 4,9,12
MKT: B15.L1(IN1) ; also sheet 4,9,12
MKT\: C14.N1(K2B:C) ; also sheet 4
N$32: B15.S1(OUT) C17.L1(8:IN)
N$36: C13.D2(2:OUT) C14.P1(K2B:D)
N$38: C15.C1(OUT) C15.H1(IN1)
N$39: C15.F1(OUT) C15.J1(IN2)
N$43: A12.N2(OUT) A12.T2(IN1)
N$45: A12.S2(OUT) A12.U2(IN2)
N$47: B11.H2(OUT) C13.C1(2:IN)
N$49: B11.E2(IN2) B12.L1(OUT)
N$55: B11.D2(IN1) B12.E1(OUT)
N$56: B11.D1(OUT) B11.F2(IN3)
N$64: A12.K2(OUT) B10.C1(IN3) B10.D1(IN4)
N$66: A12.F2(OUT) B10.A1(IN1) B10.B1(IN2)
N$70: B11.E1(IN1) B11.U1(OUT)
N$71: B15.N1(OUT) C17.F1(4:IN)
N$72: B11.H1(IN3) B11.N1(OUT)
N$77: B10.F1(IN1) B11.J1(OUT)
N$78: B10.K1(IN4) C17.H1(4:OUT)
N$82: B11.V1(OUT) C17.J1(6:IN)
N$84: A10.C1(OUT) A10.D1(IN1)
N$85: A10.B1(IN2) A10.F1(OUT) B15.P2(IN1)
N$86: B11.L2(IN3) B15.S2(OUT)
PWR_CLR\: C14.R1(K2B:S) ; also sheet 1,2,4,6
READ_DATA\: B11.J2(IN1) ; also sheet 2
SEARCH\: B11.K2(IN2) ; also sheet 2,11
SH_DTB: B10.E1(OUT) ; also sheet 6,8
SH_EN: A11.N2(11:OUT) A12.E2(IN2) ; also sheet 8
SH_EN\: A11.M2(11:IN) A12.V2(OUT) ; also sheet 8
SHIFT_CK: C17.K1(6:OUT) ; also sheet 7
ST_BLK_MK: C13.E2(5:IN) ; also sheet 7,12
ST_BLK_MK\: C13.F2(5:OUT) ; also sheet 6
ST_CK: C13.J1(6:IN) ; also sheet 4,6,7,12
ST_CK\: C13.K1(6:OUT) C16.E2(IN2)
ST_DATA: B12.A1(IN1) C13.H2(7:IN) C16.J2(OUT)
ST_DATA\: C13.J2(7:OUT)
ST_FINAL: C13.L1(8:IN) ; also sheet 4,7,9,12
ST_FINAL\: C13.M1(8:OUT) C16.F2(IN3) ; also sheet 4
ST_IDLE: C13.K2(9:IN) ; also sheet 7,12
ST_IDLE\: C13.L2(9:OUT) ; also sheet 6
ST_REV_CK: B11.S1(IN3) C13.D1(3:IN) ; also sheet 4,7,9,12
ST_REV_CK\: C13.E1(3:OUT)
SWTM: B06.P2(13:IN) B08.V1 B11.B1(IN2) ; also sheet 3,6,12
SWTM\: B06.R2(13:OUT) ; also sheet 6
SYNC_EN: B11.M2(OUT) ; also sheet 7
TP00: C15.E1(IN2) ; also sheet 3,4,6
TP00_A: B10.H1(IN2) ; also sheet 3,9
TP01: A12.J2(IN2) C15.B1(IN2) ; also sheet 3,7,9
UTS: A10.E1(IN2) B15.P1(IN1) ; also sheet 3,12
W-INH\: B11.L1(IN2) B12.H1(IN2) ; also sheet 4
WC: B11.K1(IN1) ; also sheet 1,4,12
WR_EN: C14.U1 C15.A1(IN1) ; also sheet 3,9,10,12
WR_EN\: B11.F1(IN2) C14.S1 ; also sheet 3,9
WRITE_ALL: B11.M1(IN3) B12.F1(IN1) ; also sheet 2,4
WRITE_DATA: B11.R1(IN2) B12.B1(IN2) ; also sheet 2,4,9
WRITE_OK: B11.C1(IN3) B15.R1(IN2) ; also sheet 2,6
WRITE_OK+UTS: B12.D1(IN4) B12.K1(IN4) C17.M1(8:OUT)
WRTM: B11.A1(IN1) ; also sheet 2,3,6

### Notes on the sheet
- +3V@C15U1

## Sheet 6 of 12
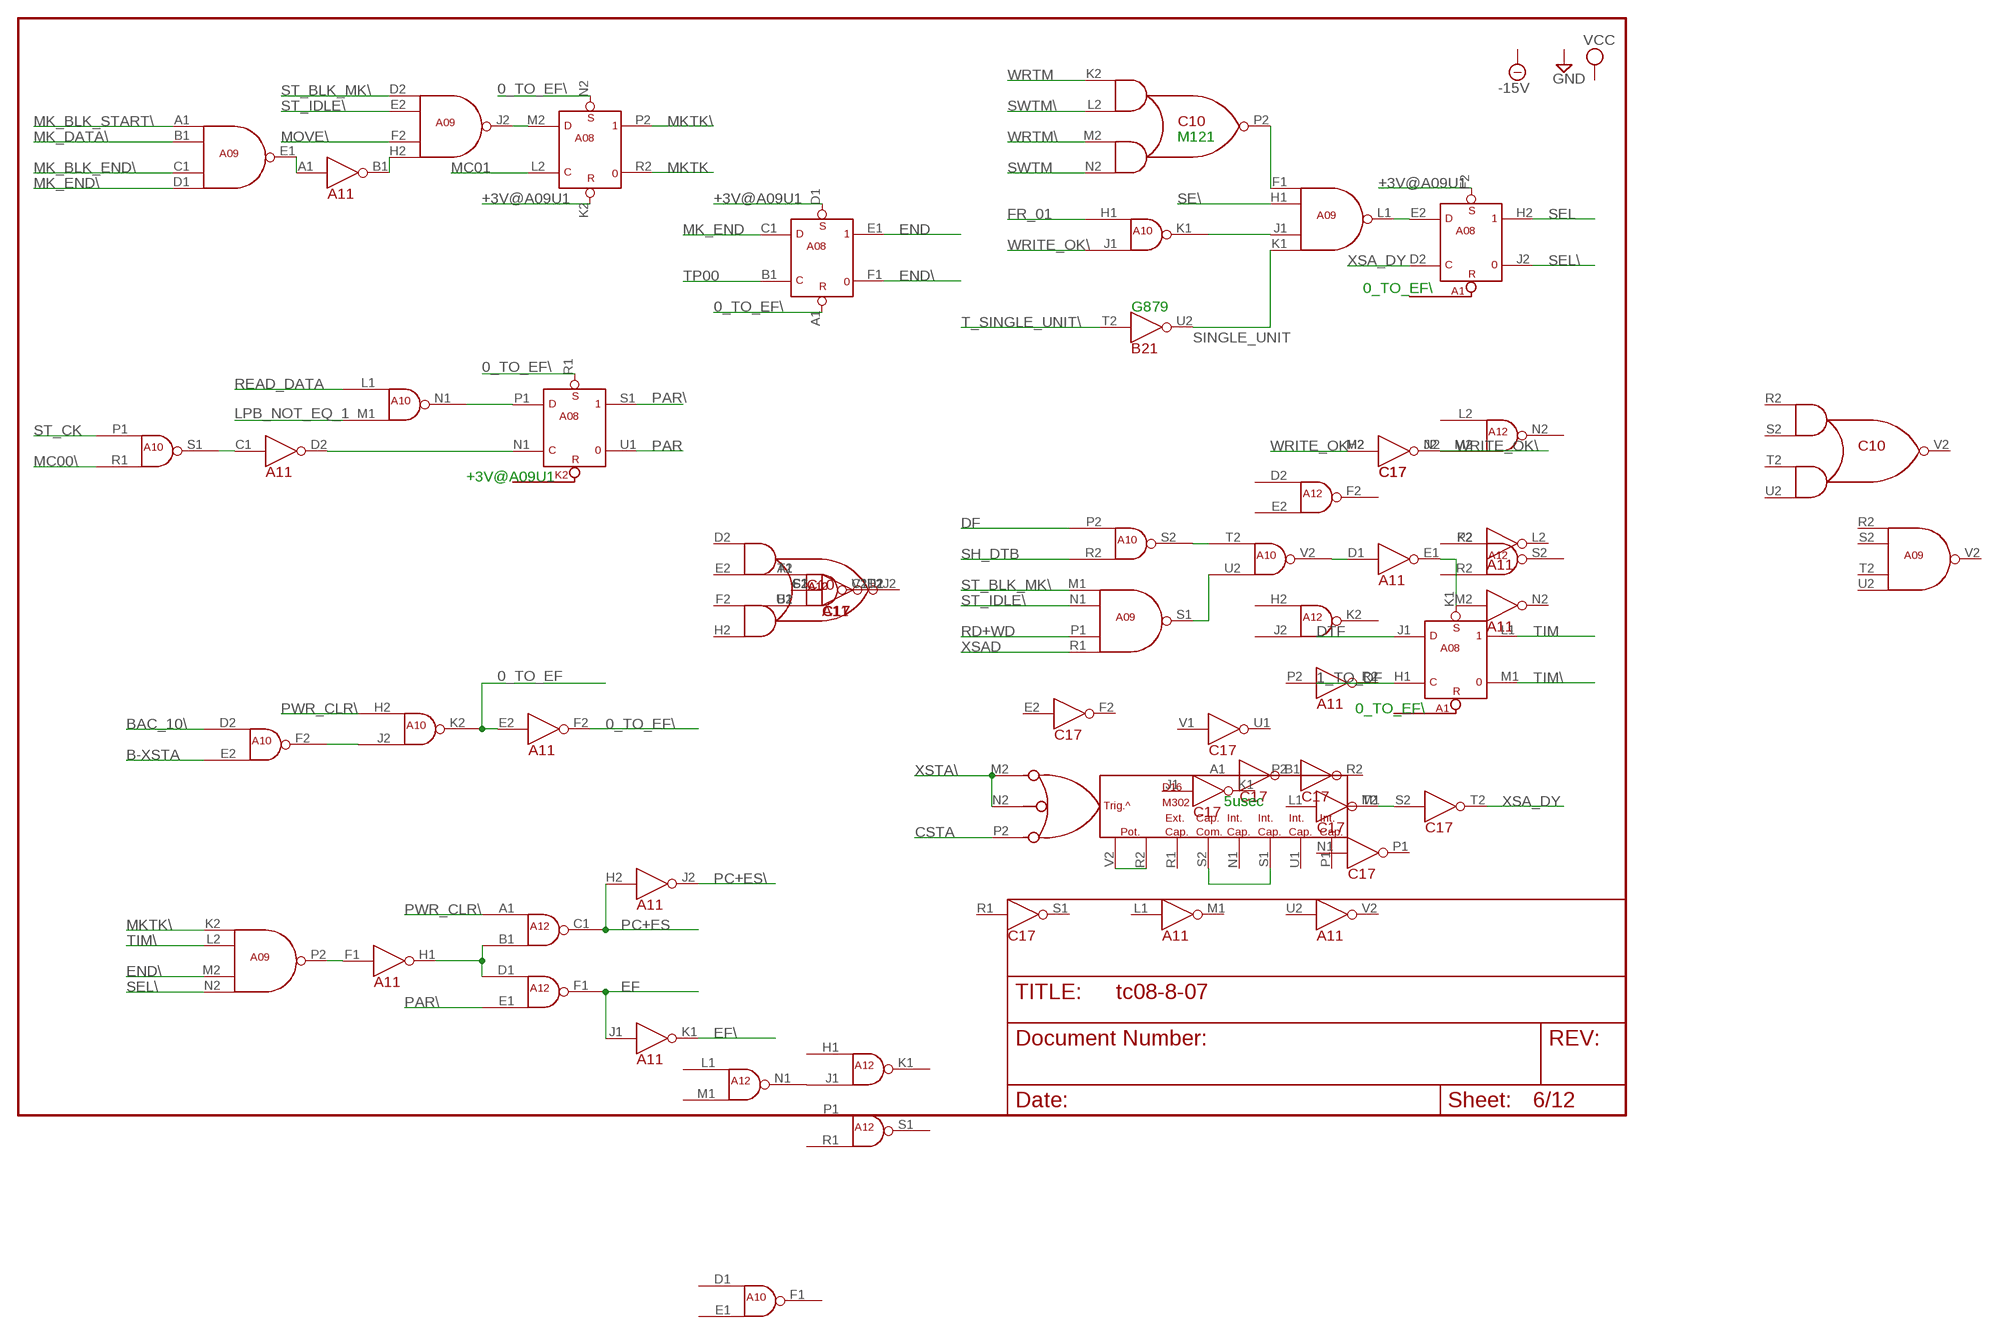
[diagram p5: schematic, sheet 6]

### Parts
B21  G879  [H807]
C10  M121  [H807]
D16  M302  [H807]

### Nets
0_TO_EF: A10.K2(OUT) A11.E2(5:IN)
0_TO_EF\: A08.A1(A1:R) A08.N2(K2:S) A08.R1(K2B:S) A11.F2(5:OUT)
1_TO_DF: A08.H1(A1C:C) ; also sheet 4
+3V@A09U1: A08.D1(A1:S) A08.F2(A1B:S) A08.K2(K2:R) ; also sheet 2,4
B-XSTA: A10.E2(IN2) ; also sheet 1,4
BAC_10\: A10.D2(IN1) ; also sheet 10,11
CSTA: D16.P2(K2) ; also sheet 1
DF: A10.P2(IN1) ; also sheet 4,12
DTF: A08.J1(A1C:D) ; also sheet 1,4,12
EF: A11.J1(6:IN) A12.F1(OUT) ; also sheet 1,12
EF\: A11.K1(6:OUT) ; also sheet 11
END: A08.E1 ; also sheet 12
END\: A08.F1 A09.M2(IN3) ; also sheet 11
FR_01: A10.H1(IN1) ; also sheet 1,2,5,12
LPB_NOT_EQ_1: A10.M1(IN2) ; also sheet 9
MC00\: A10.R1(IN2) ; also sheet 4,5
MC01: A08.L2(K2:C) ; also sheet 4,12
MK_BLK_END\: A09.C1(IN3) ; also sheet 7
MK_BLK_START\: A09.A1(IN1) ; also sheet 7
MK_DATA\: A09.B1(IN2) ; also sheet 7
MK_END: A08.C1(A1:D) ; also sheet 7
MK_END\: A09.D1(IN4) ; also sheet 7
MKTK: A08.R2 ; also sheet 12
MKTK\: A08.P2 A09.K2(IN1) ; also sheet 11
MOVE\: A09.F2(IN3) ; also sheet 2
N$34: C17.S2(15:IN) D16.T2(F2)
N$35: A09.F1(IN1) C10.P2(OUT)
N$46: A09.J1(IN3) A10.K1(OUT)
N$83: A08.E2(A1B:D) A09.L1(OUT)
N$105: A09.E1(OUT) A11.A1(1:IN)
N$106: A09.H2(IN4) A11.B1(1:OUT)
N$107: A08.M2(K2:D) A09.J2(OUT)
N$124: A10.S1(OUT) A11.C1(2:IN)
N$125: A08.P1(K2B:D) A10.N1(OUT)
N$128: A08.N1(K2B:C) A11.D2(2:OUT)
N$132: A08.K1(A1C:S) A11.E1(3:OUT)
N$137: A10.V2(OUT) A11.D1(3:IN)
N$138: A09.S1(OUT) A10.U2(IN2)
N$139: A10.S2(OUT) A10.T2(IN1)
N$150: D16.S1(H1) D16.S2(L2)
N$151: D16.R2(E2) D16.V2(D2)
N$153: A10.F2(OUT) A10.J2(IN2)
N$161: A09.P2(OUT) A11.F1(4:IN)
N$162: A11.H1(4:OUT) A12.B1(IN2) A12.D1(IN1)
PAR: A08.U1 ; also sheet 12
PAR\: A08.S1 A12.E1(IN2) ; also sheet 11
PC+ES: A11.H2(7:IN) A12.C1(OUT)
PC+ES\: A11.J2(7:OUT) ; also sheet 2
PWR_CLR\: A10.H2(IN1) A12.A1(IN1) ; also sheet 1,2,4,5
RD+WD: A09.P1(IN3) ; also sheet 2,4
READ_DATA: A10.L1(IN1) ; also sheet 2,4
SE\: A09.H1(IN2) ; also sheet 2
SEL: A08.H2 ; also sheet 12
SEL\: A08.J2 A09.N2(IN4) ; also sheet 11
SH_DTB: A10.R2(IN2) ; also sheet 5,8
SINGLE_UNIT: A09.K1(IN4) B21.U2(OUT)
ST_BLK_MK\: A09.D2(IN1) A09.M1(IN1) ; also sheet 5
ST_CK: A10.P1(IN1) ; also sheet 4,5,7,12
ST_IDLE\: A09.E2(IN2) A09.N1(IN2) ; also sheet 5
SWTM: C10.N2(IN2B) ; also sheet 3,5,12
SWTM\: C10.L2(IN1B) ; also sheet 5
T_SINGLE_UNIT\: B21.T2(IN) ; also sheet 12
TIM: A08.L1 ; also sheet 12
TIM\: A08.M1 A09.L2(IN2) ; also sheet 11
TP00: A08.B1(A1:C) ; also sheet 3,4,5
WRITE_OK: C17.H2(7:IN) ; also sheet 2,5
WRITE_OK\: A10.J1(IN2) C17.J2(7:OUT)
WRTM: C10.K2(IN1A) ; also sheet 2,3,5
WRTM\: C10.M2(IN2A) ; also sheet 2
XSA_DY: A08.D2(A1B:C) C17.T2(15:OUT) ; also sheet 2
XSAD: A09.R1(IN4) ; also sheet 1
XSTA\: D16.M2(H2) D16.N2(J2) ; also sheet 1,3
Unconnected: C10.U1 C10.V1 D16.D1 D16.D2 D16.E1 D16.E2 D16.F1 D16.F2 D16.H1 D16.H2 D16.J1 D16.J2 D16.K2 D16.L2 D16.N1(D1) D16.P1(E1) D16.R1(F1) D16.U1(J1)

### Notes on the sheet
- M121
- 0_TO_EF\
- G879
- +3V@A09U1
- 0_TO_EF\
- 5usec

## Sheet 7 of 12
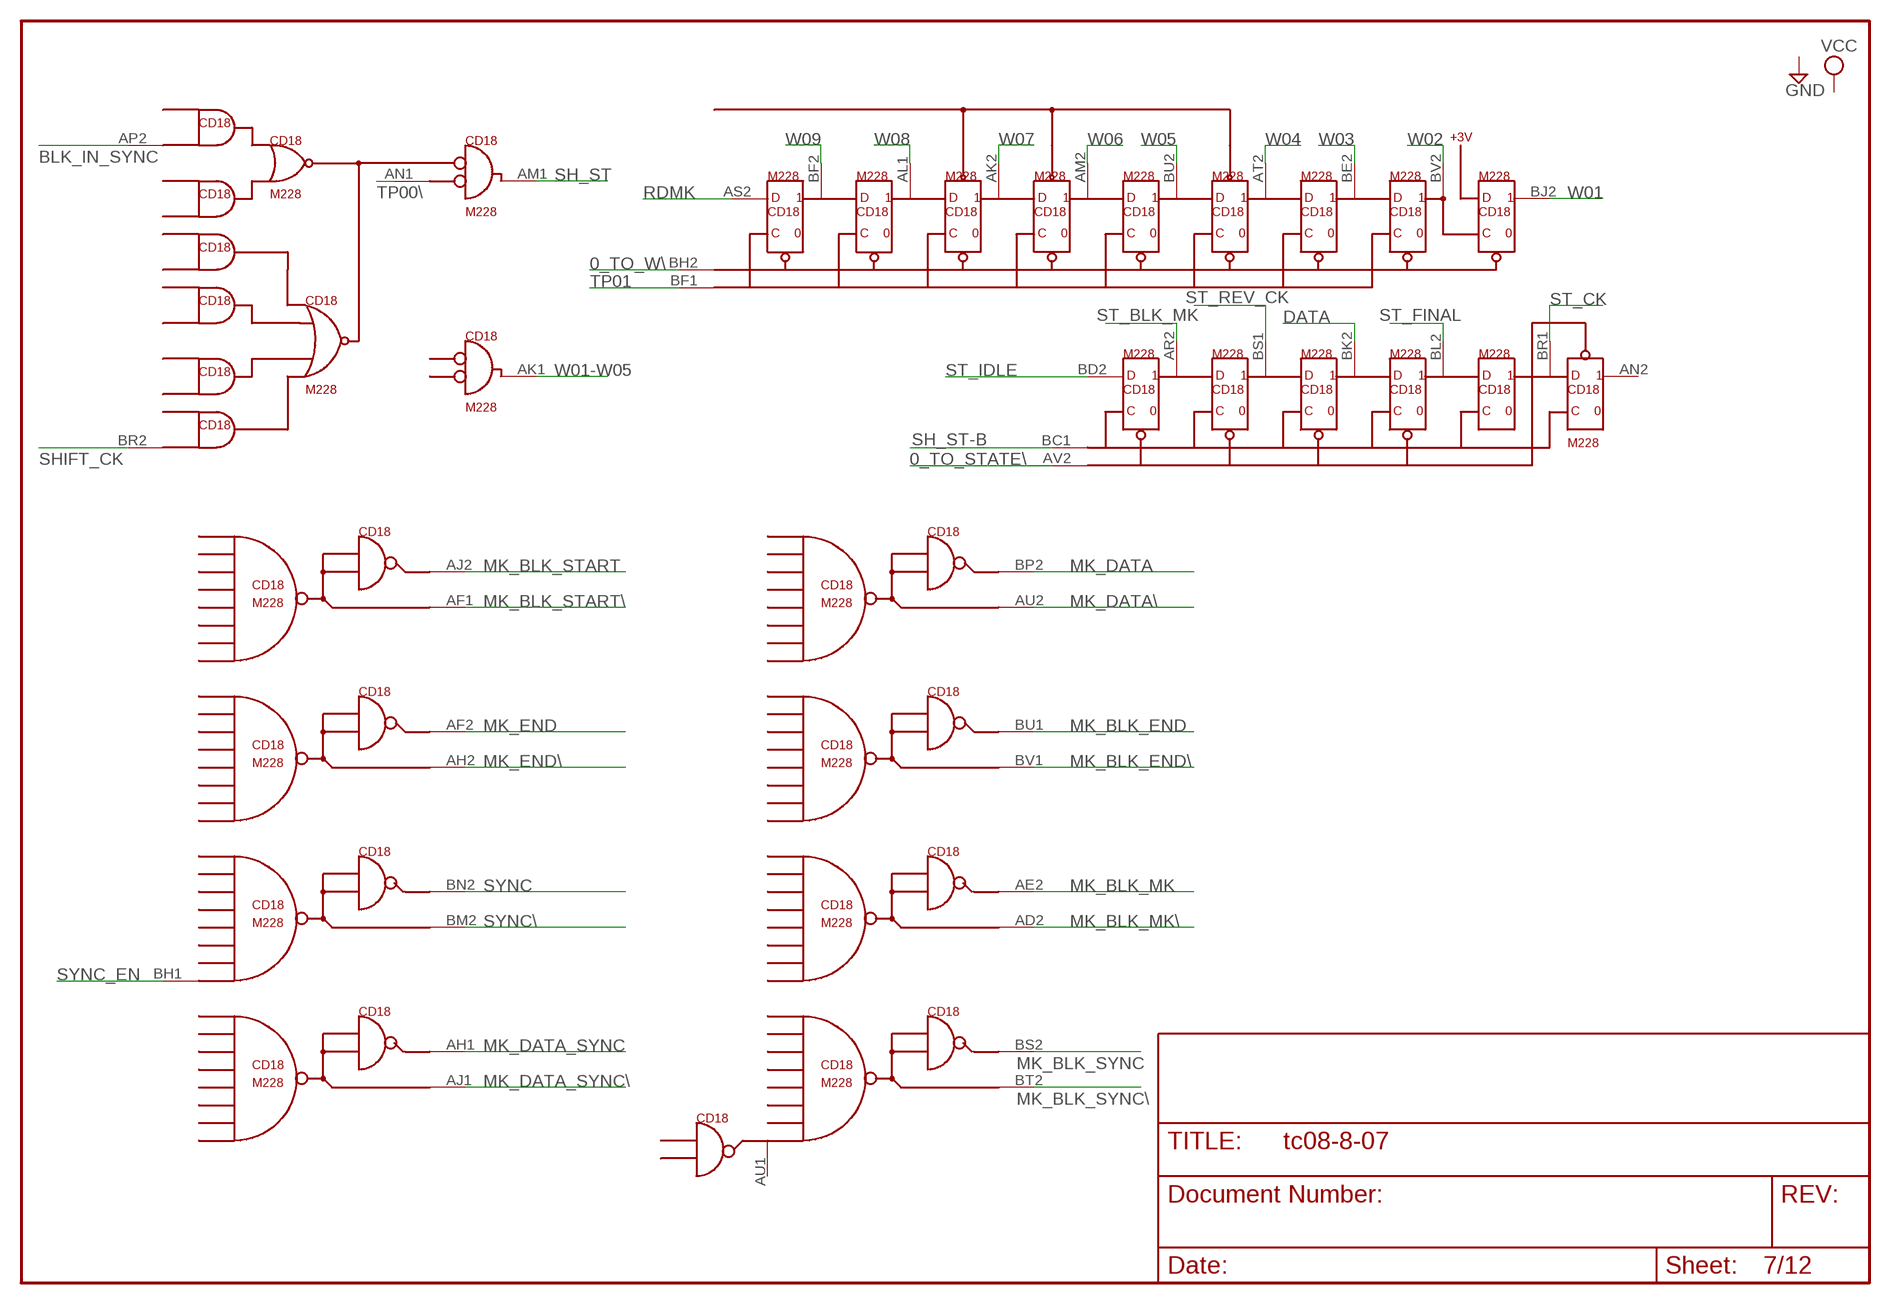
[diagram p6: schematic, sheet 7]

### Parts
CD18  M228  [H807-2]

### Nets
0_TO_STATE\: CD18.AV2 ; also sheet 3
0_TO_W\: CD18.BH2 ; also sheet 3
BLK_IN_SYNC: CD18.AP2 ; also sheet 4
DATA: CD18.BK2 ; also sheet 5,12
MK_BLK_END: CD18.BU1 ; also sheet 9
MK_BLK_END\: CD18.BV1 ; also sheet 6
MK_BLK_MK: CD18.AE2 ; also sheet 4
MK_BLK_MK\: CD18.AD2
MK_BLK_START: CD18.AJ2
MK_BLK_START\: CD18.AF1 ; also sheet 6
MK_BLK_SYNC: CD18.BS2
MK_BLK_SYNC\: CD18.BT2
MK_DATA: CD18.BP2
MK_DATA\: CD18.AU2 ; also sheet 6
MK_DATA_SYNC: CD18.AH1
MK_DATA_SYNC\: CD18.AJ1
MK_END: CD18.AF2 ; also sheet 6
MK_END\: CD18.AH2 ; also sheet 6
RDMK: CD18.AS2 ; also sheet 10
SH_ST: CD18.AM1 ; also sheet 1
SH_ST-B: CD18.BC1 ; also sheet 1
SHIFT_CK: CD18.BR2 ; also sheet 5
ST_BLK_MK: CD18.AR2 ; also sheet 5,12
ST_CK: CD18.BR1 ; also sheet 4,5,6,12
ST_FINAL: CD18.BL2 ; also sheet 4,5,9,12
ST_IDLE: CD18.BD2 ; also sheet 5,12
ST_REV_CK: CD18.BS1 ; also sheet 4,5,9,12
SYNC: CD18.BN2 ; also sheet 4
SYNC\: CD18.BM2
SYNC_EN: CD18.BH1 ; also sheet 5
TP00\: CD18.AN1 ; also sheet 3,4
TP01: CD18.BF1 ; also sheet 3,5,9
W01: CD18.BJ2 ; also sheet 12
W01-W05: CD18.AK1
W02: CD18.BV2 ; also sheet 12
W03: CD18.BE2 ; also sheet 12
W04: CD18.AT2 ; also sheet 12
W05: CD18.BU2 ; also sheet 12
W06: CD18.AM2 ; also sheet 12
W07: CD18.AK2 ; also sheet 12
W08: CD18.AL1 ; also sheet 12
W09: CD18.BF2 ; also sheet 12
Unconnected: CD18.AN2 CD18.AU1

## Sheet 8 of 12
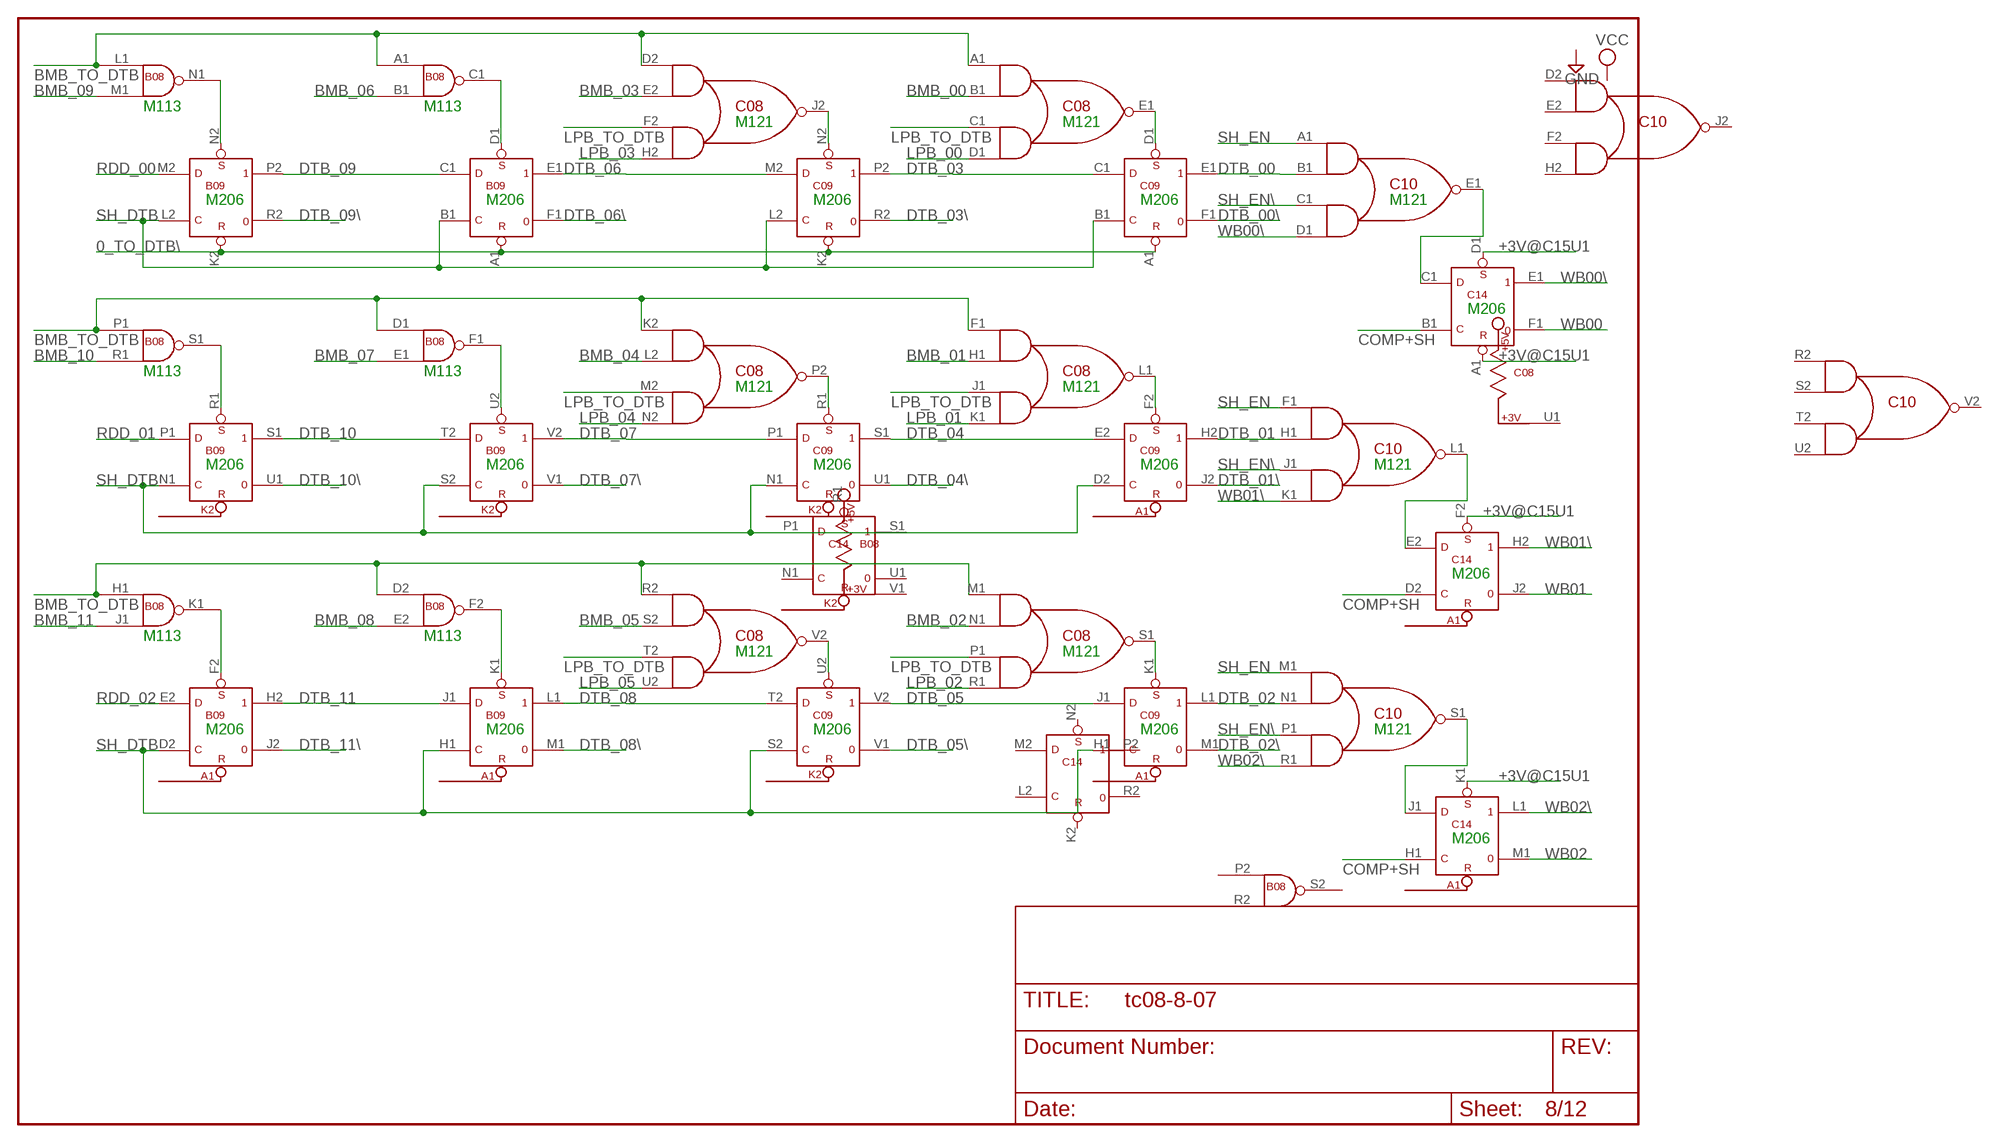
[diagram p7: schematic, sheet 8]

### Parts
B09  M206  M206X  [H807]
C09  M206  M206X  [H807]

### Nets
0_TO_DTB\: B09.A1(A1:R) B09.K2(K2:R) C09.A1(A1:R) C09.K2(K2:R) ; also sheet 5
+3V@C15U1: C14.A1(A1:R) C14.D1(A1:S) C14.F2(A1B:S) C14.K1(A1C:S) ; also sheet 3,5
BMB_00: C08.B1(IN1B) ; also sheet 10
BMB_01: C08.H1(IN1B) ; also sheet 10
BMB_02: C08.N1(IN1B) ; also sheet 10
BMB_03: C08.E2(IN1B) ; also sheet 10
BMB_04: C08.L2(IN1B) ; also sheet 10
BMB_05: C08.S2(IN1B) ; also sheet 10
BMB_06: B08.B1(IN2) ; also sheet 10
BMB_07: B08.E1(IN2) ; also sheet 10
BMB_08: B08.E2(IN2) ; also sheet 10
BMB_09: B08.M1(IN2) ; also sheet 10
BMB_10: B08.R1(IN2) ; also sheet 10
BMB_11: B08.J1(IN2) ; also sheet 10
BMB_TO_DTB: B08.A1(IN1) B08.D1(IN1) B08.D2(IN1) B08.H1(IN1) B08.L1(IN1) B08.P1(IN1) C08.A1(IN1A) C08.D2(IN1A) C08.F1(IN1A) C08.K2(IN1A) C08.M1(IN1A) C08.R2(IN1A) ; also sheet 1
COMP+SH: C14.B1(A1:C) C14.D2(A1B:C) C14.H1(A1C:C) ; also sheet 5
DTB_00: C09.E1 C10.B1(IN1B) ; also sheet 9,12
DTB_00\: C09.F1 ; also sheet 11
DTB_01: C09.H2 C10.H1(IN1B) ; also sheet 9,12
DTB_01\: C09.J2 ; also sheet 11
DTB_02: C09.L1 C10.N1(IN1B) ; also sheet 9,12
DTB_02\: C09.M1 ; also sheet 11
DTB_03: C09.C1(A1:D) C09.P2 ; also sheet 12
DTB_03\: C09.R2 ; also sheet 11
DTB_04: C09.E2(A1B:D) C09.S1 ; also sheet 12
DTB_04\: C09.U1 ; also sheet 11
DTB_05: C09.J1(A1C:D) C09.V2 ; also sheet 12
DTB_05\: C09.V1 ; also sheet 11
DTB_06: B09.E1 C09.M2(K2:D) ; also sheet 12
DTB_06\: B09.F1 ; also sheet 11
DTB_07: B09.V2 C09.P1(K2B:D) ; also sheet 12
DTB_07\: B09.V1 ; also sheet 11
DTB_08: B09.L1 C09.T2(K2C:D) ; also sheet 12
DTB_08\: B09.M1 ; also sheet 11
DTB_09: B09.C1(A1:D) B09.P2 ; also sheet 12
DTB_09\: B09.R2 ; also sheet 11
DTB_10: B09.S1 B09.T2(K2C:D) ; also sheet 12
DTB_10\: B09.U1 ; also sheet 11
DTB_11: B09.H2 B09.J1(A1C:D) ; also sheet 12
DTB_11\: B09.J2 ; also sheet 11
LPB_00: C08.D1(IN2B) ; also sheet 9,12
LPB_01: C08.K1(IN2B) ; also sheet 9,12
LPB_02: C08.R1(IN2B) ; also sheet 9,12
LPB_03: C08.H2(IN2B) ; also sheet 9,12
LPB_04: C08.N2(IN2B) ; also sheet 9,12
LPB_05: C08.U2(IN2B) ; also sheet 9,12
LPB_TO_DTB: C08.C1(IN2A) C08.F2(IN2A) C08.J1(IN2A) C08.M2(IN2A) C08.P1(IN2A) C08.T2(IN2A) ; also sheet 9
N$73: B08.N1(OUT) B09.N2(K2:S)
N$91: B08.S1(OUT) B09.R1(K2B:S)
N$92: B08.K1(OUT) B09.F2(A1B:S)
N$97: B08.C1(OUT) B09.D1(A1:S)
N$104: C08.J2(OUT) C09.N2(K2:S)
N$112: B08.F1(OUT) B09.U2(K2C:S)
N$113: B08.F2(OUT) B09.K1(A1C:S)
N$129: C08.V2(OUT) C09.U2(K2C:S)
N$142: C08.P2(OUT) C09.R1(K2B:S)
N$146: C08.E1(OUT) C09.D1(A1:S)
N$147: C08.L1(OUT) C09.F2(A1B:S)
N$148: C08.S1(OUT) C09.K1(A1C:S)
N$155: C10.L1(OUT) C14.E2(A1B:D)
N$185: C10.E1(OUT) C14.C1(A1:D)
N$193: C10.S1(OUT) C14.J1(A1C:D)
RDD_00: B09.M2(K2:D) ; also sheet 9,10
RDD_01: B09.P1(K2B:D) ; also sheet 9,10
RDD_02: B09.E2(A1B:D) ; also sheet 9,10
SH_DTB: B09.B1(A1:C) B09.D2(A1B:C) B09.H1(A1C:C) B09.L2(K2:C) B09.N1(K2B:C) B09.S2(K2C:C) C09.B1(A1:C) C09.D2(A1B:C) C09.H1(A1C:C) C09.L2(K2:C) C09.N1(K2B:C) C09.S2(K2C:C) ; also sheet 5,6
SH_EN: C10.A1(IN1A) C10.F1(IN1A) C10.M1(IN1A) ; also sheet 5
SH_EN\: C10.C1(IN2A) C10.J1(IN2A) C10.P1(IN2A) ; also sheet 5
WB00: C14.F1 ; also sheet 9,10,12
WB00\: C10.D1(IN2B) C14.E1 ; also sheet 10
WB01: C14.J2 ; also sheet 9,10,12
WB01\: C10.K1(IN2B) C14.H2 ; also sheet 10
WB02: C14.M1 ; also sheet 9,10,12
WB02\: C10.R1(IN2B) C14.L1 ; also sheet 10

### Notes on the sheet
- M113 | M113
- M121 | M121
- M206 | M206 | M206 | M206 | M121
- M206
- M113 | M113
- M121 | M121
- M206 | M206 | M206 | M206 | M121
- M206
- M113 | M113
- M121 | M121
- M206 | M206 | M206 | M206 | M121
- M206

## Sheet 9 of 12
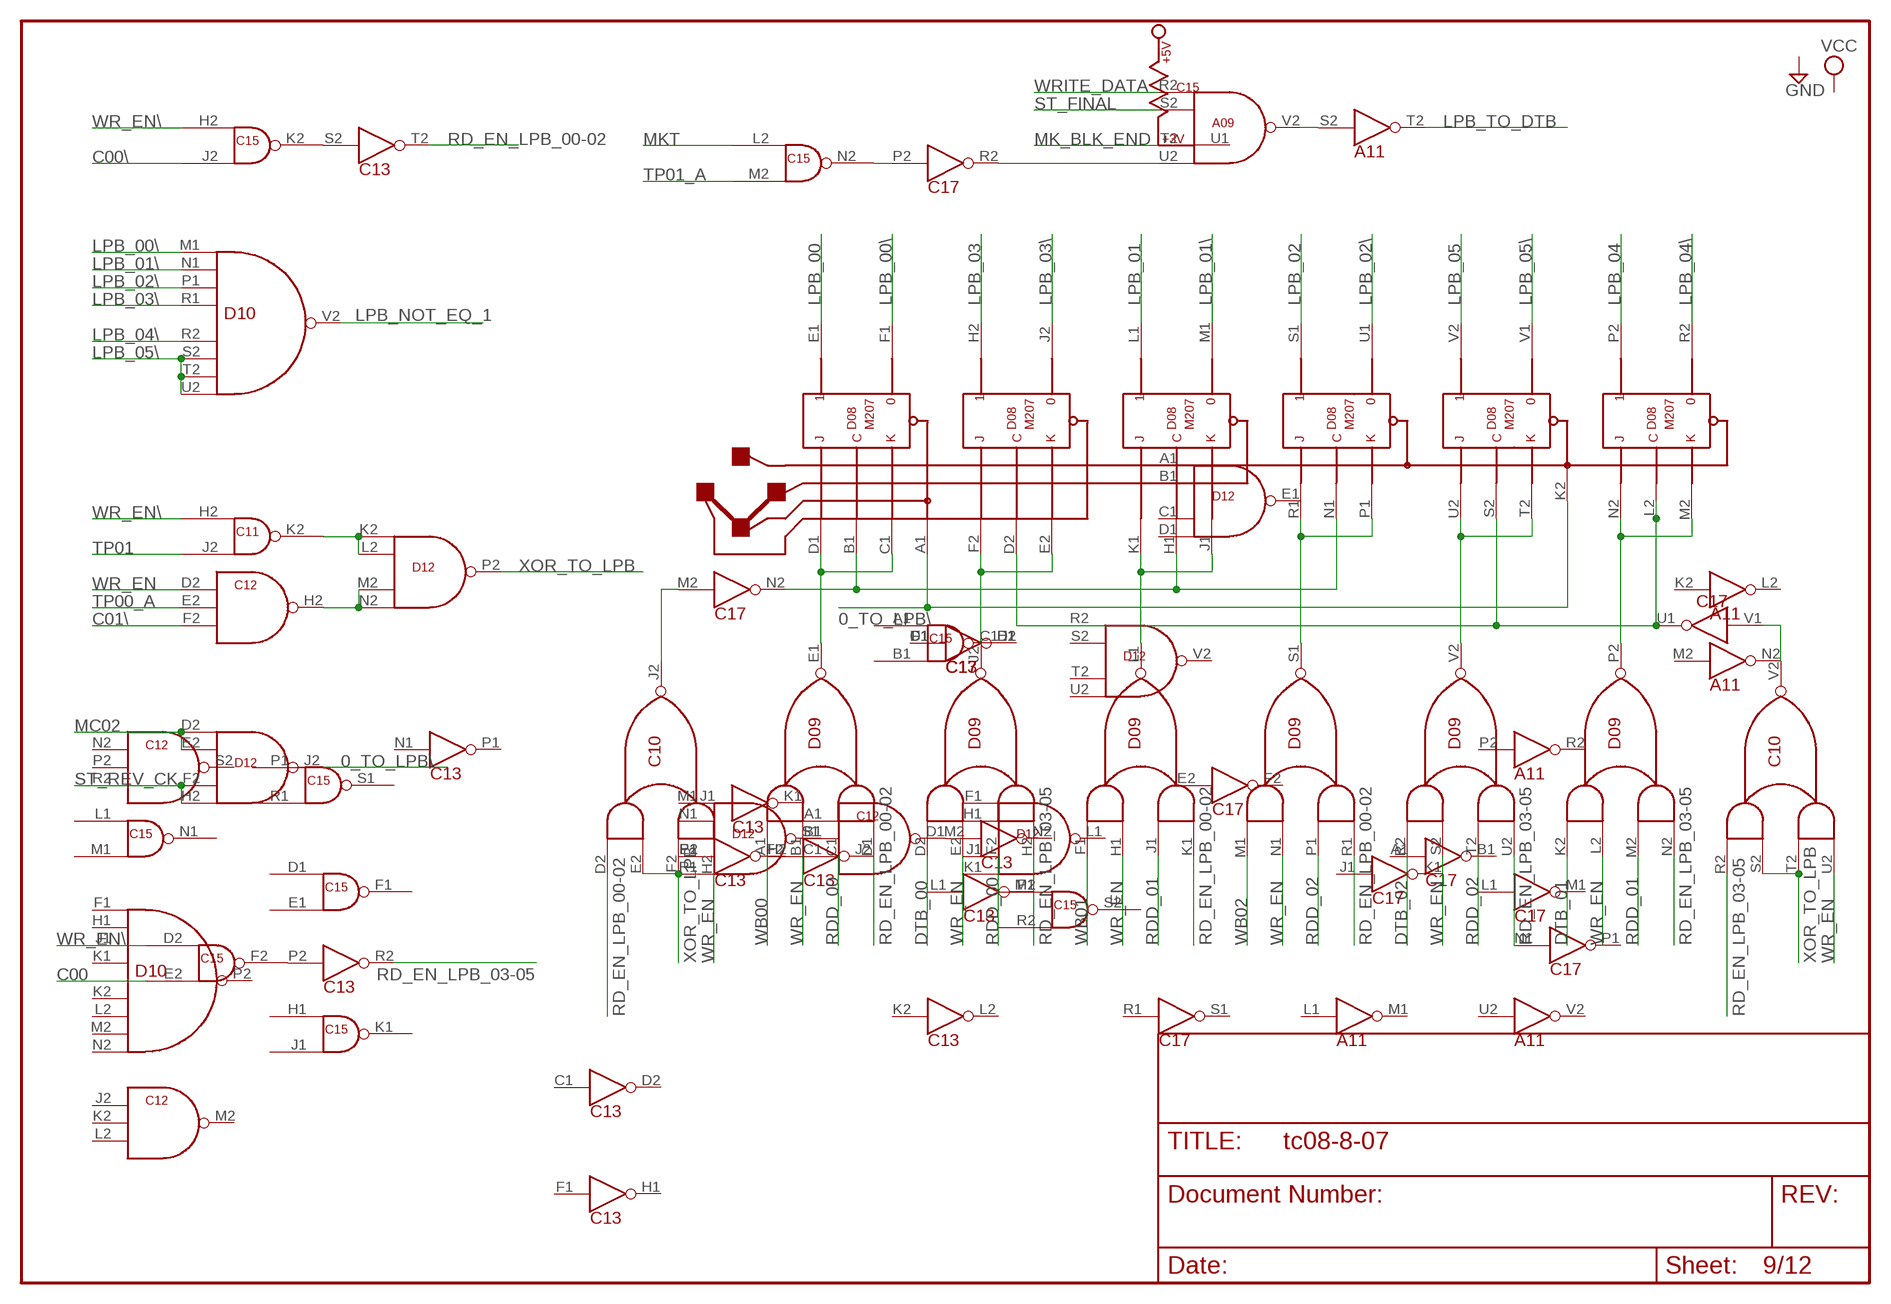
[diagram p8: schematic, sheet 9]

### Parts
D08  M207  [H807]

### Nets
0_TO_LPB\: D08.A1 D08.K2 D12.J2(OUT)
C00: C15.E2(IN2) ; also sheet 4,5,12
C00\: C15.J2(IN2) ; also sheet 4,5
C01\: C12.F2(IN3) ; also sheet 4,5
DTB_00: D09.D2(IN1A) ; also sheet 8,12
DTB_01: D09.K2(IN1A) ; also sheet 8,12
DTB_02: D09.R2(IN1A) ; also sheet 8,12
LPB_00: D08.E1 ; also sheet 8,12
LPB_00\: D08.F1 D10.M1(IN1)
LPB_01: D08.L1 ; also sheet 8,12
LPB_01\: D08.M1 D10.N1(IN2)
LPB_02: D08.S1 ; also sheet 8,12
LPB_02\: D08.U1 D10.P1(IN3)
LPB_03: D08.H2 ; also sheet 8,12
LPB_03\: D08.J2 D10.R1(IN4)
LPB_04: D08.P2 ; also sheet 8,12
LPB_04\: D08.R2 D10.R2(IN5)
LPB_05: D08.V2 ; also sheet 8,12
LPB_05\: D08.V1 D10.S2(IN6) D10.T2(IN7) D10.U2(IN8)
LPB_NOT_EQ_1: D10.V2(OUT) ; also sheet 6
LPB_TO_DTB: A11.T2(15:OUT) ; also sheet 8
MC02: D12.D2(IN1) D12.E2(IN2) ; also sheet 4,5,12
MK_BLK_END: A09.T2(IN3) ; also sheet 7
MKT: C15.L2(IN1) ; also sheet 4,5,12
N$93: D08.C1 D08.D1 D09.E1(OUT)
N$94: D08.E2 D08.F2 D09.J2(OUT)
N$95: D08.J1 D08.K1 D09.L1(OUT)
N$96: D08.P1 D08.R1 D09.S1(OUT)
N$99: D08.T2 D08.U2 D09.V2(OUT)
N$100: D08.M2 D08.N2 D09.P2(OUT)
N$101: C17.U1(14:OUT) D08.D2 D08.L2 D08.S2
N$103: C17.N2(11:OUT) D08.B1 D08.H1 D08.N1
N$108: C10.J2(OUT) C17.M2(11:IN)
N$109: C10.V2(OUT) C17.V1(14:IN)
N$111: A09.U2(IN4) C17.R2(13:OUT)
N$114: A09.V2(OUT) A11.S2(15:IN)
N$115: C15.N2(OUT) C17.P2(13:IN)
N$116: C13.S2(15:IN) C15.K2(OUT)
N$117: C12.H2(OUT) D12.M2(IN3) D12.N2(IN4)
N$118: C11.K2(OUT) D12.K2(IN1) D12.L2(IN2)
N$119: C13.P2(13:IN) C15.F2(OUT)
RD_EN_LPB_00-02: C10.D2(IN1A) C13.T2(15:OUT) D09.D1(IN2B) D09.K1(IN2B) D09.R1(IN2B)
RD_EN_LPB_03-05: C10.R2(IN1A) C13.R2(13:OUT) D09.H2(IN2B) D09.N2(IN2B) D09.U2(IN2B)
RDD_00: D09.C1(IN2A) D09.F2(IN2A) ; also sheet 8,10
RDD_01: D09.J1(IN2A) D09.M2(IN2A) ; also sheet 8,10
RDD_02: D09.P1(IN2A) D09.T2(IN2A) ; also sheet 8,10
ST_FINAL: A09.S2(IN2) ; also sheet 4,5,7,12
ST_REV_CK: D12.F2(IN3) D12.H2(IN4) ; also sheet 4,5,7,12
TP00_A: C12.E2(IN2) ; also sheet 3,5
TP01: C11.J2(IN2) ; also sheet 3,5,7
TP01_A: C15.M2(IN2) ; also sheet 3,4
WB00: D09.A1(IN1A) ; also sheet 8,10,12
WB01: D09.F1(IN1A) ; also sheet 8,10,12
WB02: D09.M1(IN1A) ; also sheet 8,10,12
WR_EN: C10.H2(IN2B) C10.U2(IN2B) C12.D2(IN1) D09.B1(IN1B) D09.E2(IN1B) D09.H1(IN1B) D09.L2(IN1B) D09.N1(IN1B) D09.S2(IN1B) ; also sheet 3,5,10,12
WR_EN\: C11.H2(IN1) C15.D2(IN1) C15.H2(IN1) ; also sheet 3,5
WRITE_DATA: A09.R2(IN1) ; also sheet 2,4,5
XOR_TO_LPB: C10.E2(IN1B) C10.F2(IN2A) C10.S2(IN1B) C10.T2(IN2A) D12.P2(OUT)

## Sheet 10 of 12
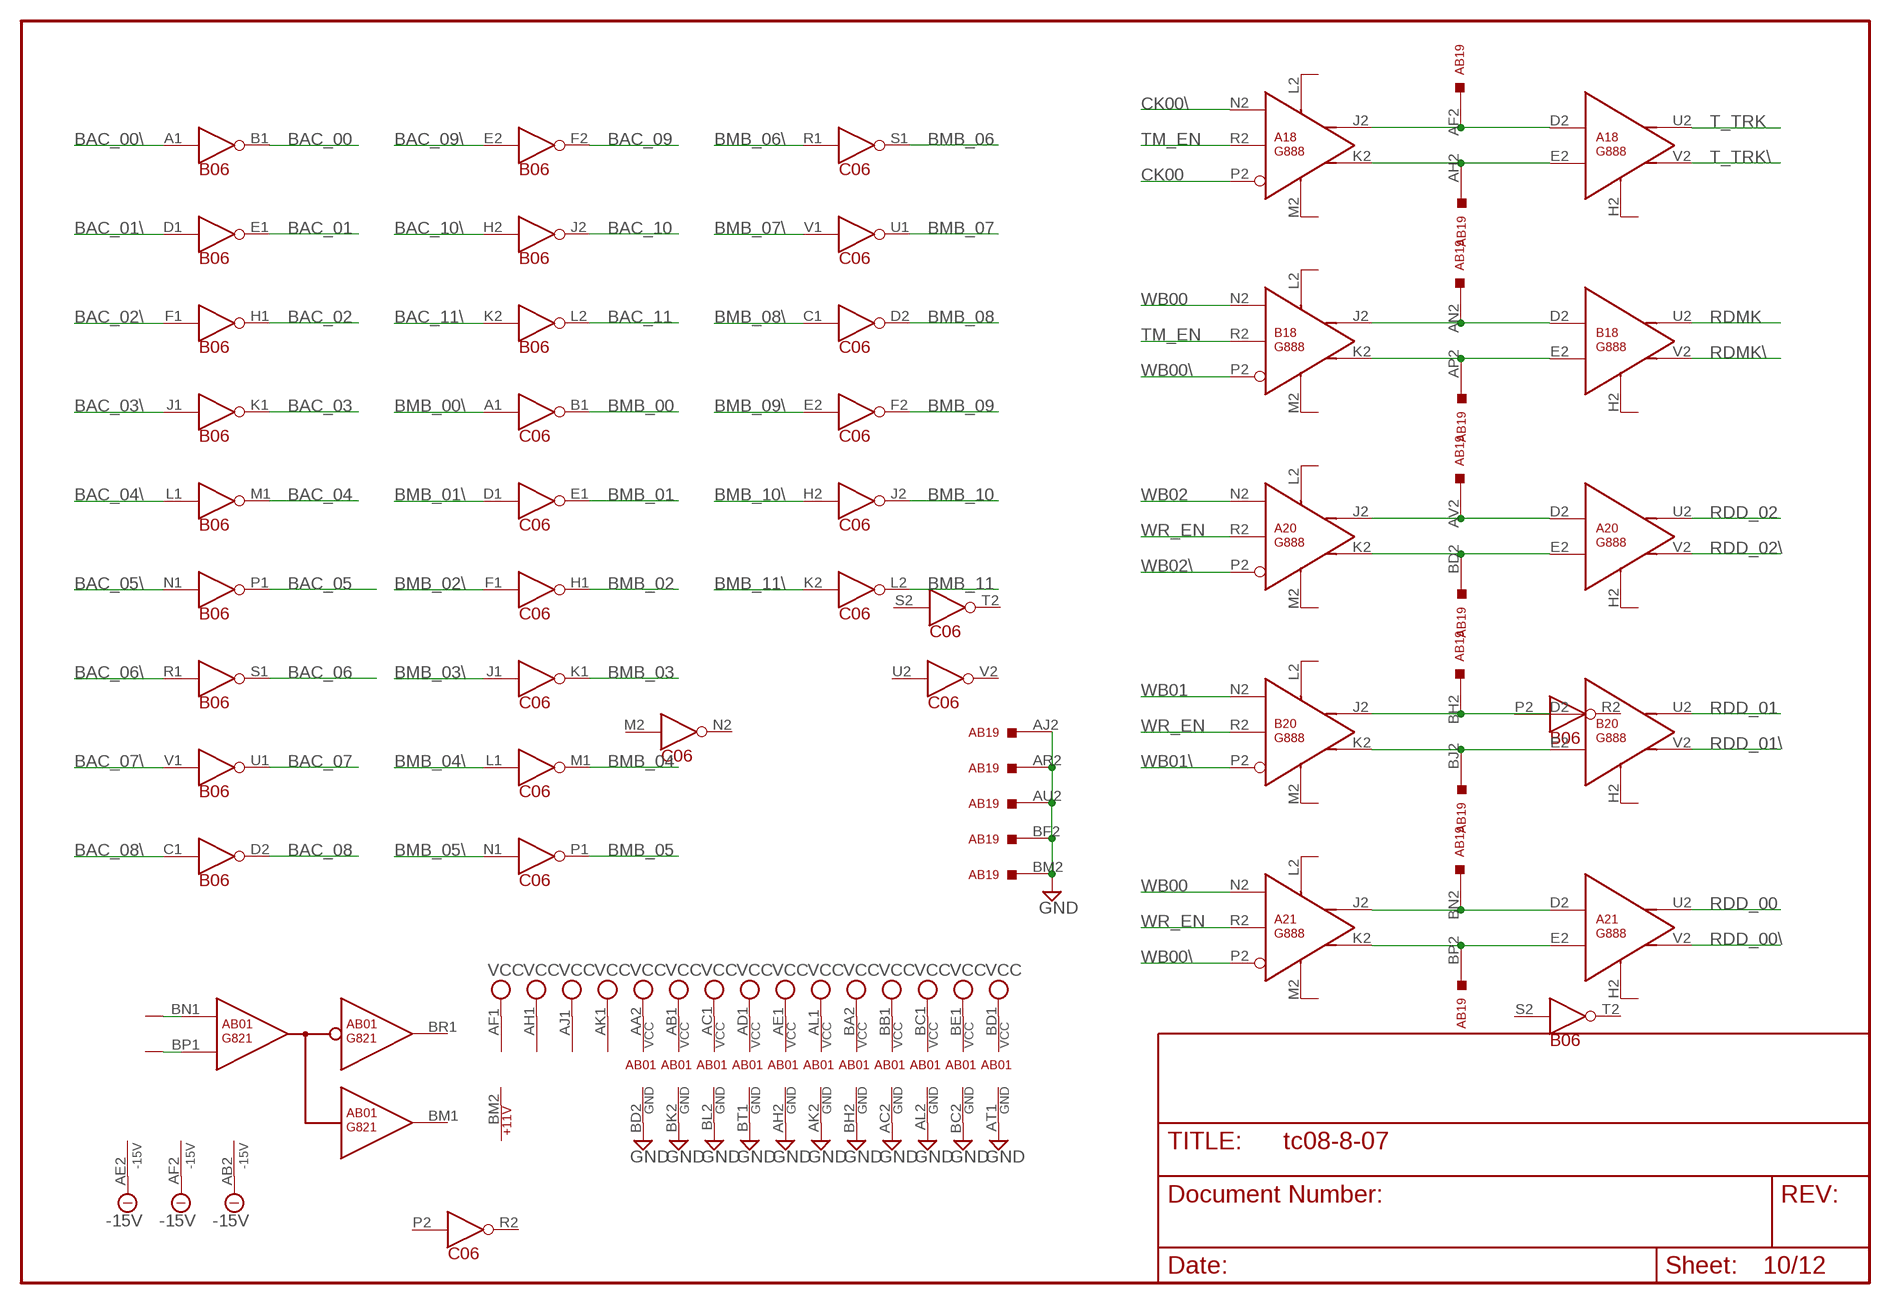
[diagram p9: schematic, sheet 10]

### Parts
A18  G888  [H807]
A20  G888  [H807]
A21  G888  [H807]
AB01  G821  [H807-2]
AB19  W032  [H807-2]
B18  G888  [H807]
B20  G888  [H807]

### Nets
+11V: AB01.BM2(+11V)
-15V [Power]: AB01.AB2(-15V) AB01.AE2(-15V) AB01.AF2(-15V)
BAC_00: B06.B1(1:OUT) ; also sheet 2
BAC_00\: B06.A1(1:IN) ; also sheet 3,11
BAC_01: B06.E1(3:OUT) ; also sheet 2
BAC_01\: B06.D1(3:IN) ; also sheet 3,11
BAC_02: B06.H1(4:OUT) ; also sheet 2
BAC_02\: B06.F1(4:IN) ; also sheet 3,11
BAC_03: B06.K1(6:OUT) ; also sheet 2
BAC_03\: B06.J1(6:IN) ; also sheet 3,11
BAC_04: B06.M1(8:OUT) ; also sheet 2
BAC_04\: B06.L1(8:IN) ; also sheet 3,11
BAC_05: B06.P1(10:OUT) ; also sheet 2
BAC_05\: B06.N1(10:IN) ; also sheet 11
BAC_06: B06.S1(12:OUT) ; also sheet 1,2
BAC_06\: B06.R1(12:IN) ; also sheet 11
BAC_07: B06.U1(14:OUT) ; also sheet 1,2
BAC_07\: B06.V1(14:IN) ; also sheet 11
BAC_08: B06.D2(2:OUT) ; also sheet 1,2
BAC_08\: B06.C1(2:IN) ; also sheet 11
BAC_09: B06.F2(5:OUT) ; also sheet 2
BAC_09\: B06.E2(5:IN) ; also sheet 11
BAC_10: B06.J2(7:OUT)
BAC_10\: B06.H2(7:IN) ; also sheet 6,11
BAC_11: B06.L2(9:OUT)
BAC_11\: B06.K2(9:IN) ; also sheet 4,11
BMB_00: C06.B1(1:OUT) ; also sheet 8
BMB_00\: C06.A1(1:IN) ; also sheet 11
BMB_01: C06.E1(3:OUT) ; also sheet 8
BMB_01\: C06.D1(3:IN) ; also sheet 11
BMB_02: C06.H1(4:OUT) ; also sheet 8
BMB_02\: C06.F1(4:IN) ; also sheet 11
BMB_03: C06.K1(6:OUT) ; also sheet 8
BMB_03\: C06.J1(6:IN) ; also sheet 11
BMB_04: C06.M1(8:OUT) ; also sheet 8
BMB_04\: C06.L1(8:IN) ; also sheet 11
BMB_05: C06.P1(10:OUT) ; also sheet 8
BMB_05\: C06.N1(10:IN) ; also sheet 11
BMB_06: C06.S1(12:OUT) ; also sheet 8
BMB_06\: C06.R1(12:IN) ; also sheet 11
BMB_07: C06.U1(14:OUT) ; also sheet 8
BMB_07\: C06.V1(14:IN) ; also sheet 11
BMB_08: C06.D2(2:OUT) ; also sheet 8
BMB_08\: C06.C1(2:IN) ; also sheet 11
BMB_09: C06.F2(5:OUT) ; also sheet 8
BMB_09\: C06.E2(5:IN) ; also sheet 11
BMB_10: C06.J2(7:OUT) ; also sheet 8
BMB_10\: C06.H2(7:IN) ; also sheet 11
BMB_11: C06.L2(9:OUT) ; also sheet 8
BMB_11\: C06.K2(9:IN) ; also sheet 11
CK00: A18.P2 ; also sheet 3
CK00\: A18.N2 ; also sheet 3
GND [Power]: AB01.AC2(GND) AB01.AH2(GND) AB01.AK2(GND) AB01.AL2(GND) AB01.AT1(GND) AB01.BC2(GND) AB01.BD2(GND) AB01.BH2(GND) AB01.BK2(GND) AB01.BL2(GND) AB01.BT1(GND) AB19.AJ2 AB19.AR2 AB19.AU2 AB19.BF2 AB19.BM2 ; also sheet 1,2,4,11,12
N$123: A18.D2 A18.J2 AB19.AF2
N$126: A18.E2 A18.K2 AB19.AH2
N$127: AB19.AN2 B18.D2 B18.J2
N$130: AB19.AP2 B18.E2 B18.K2
N$131: A20.D2 A20.J2 AB19.AV2
N$133: A20.E2 A20.K2 AB19.BD2
N$134: AB19.BH2 B20.D2 B20.J2
N$135: AB19.BJ2 B20.E2 B20.K2
N$136: A21.D2 A21.J2 AB19.BN2
N$140: A21.E2 A21.K2 AB19.BP2
NC: A18.H2 A18.L2 A18.M2 A20.H2 A20.L2 A20.M2 A21.H2 A21.L2 A21.M2 AB01.BN1 AB01.BP1 B18.H2 B18.L2 B18.M2 B20.H2 B20.L2 B20.M2 ; also sheet 2,3,11,12
RDD_00: A21.U2 ; also sheet 8,9
RDD_00\: A21.V2
RDD_01: B20.U2 ; also sheet 8,9
RDD_01\: B20.V2
RDD_02: A20.U2 ; also sheet 8,9
RDD_02\: A20.V2
RDMK: B18.U2 ; also sheet 7
RDMK\: B18.V2
T_TRK: A18.U2 ; also sheet 3
T_TRK\: A18.V2 ; also sheet 3
TM_EN: A18.R2 B18.R2 ; also sheet 3
VCC [Power]: AB01.AA2(VCC) AB01.AB1(VCC) AB01.AC1(VCC) AB01.AD1(VCC) AB01.AE1(VCC) AB01.AF1(VCC) AB01.AH1(VCC) AB01.AJ1(VCC) AB01.AK1(VCC) AB01.AL1(VCC) AB01.BA2(VCC) AB01.BB1(VCC) AB01.BC1(VCC) AB01.BD1(VCC) AB01.BE1(VCC)
WB00: A21.N2 B18.N2 ; also sheet 8,9,12
WB00\: A21.P2 B18.P2 ; also sheet 8
WB01: B20.N2 ; also sheet 8,9,12
WB01\: B20.P2 ; also sheet 8
WB02: A20.N2 ; also sheet 8,9,12
WB02\: A20.P2 ; also sheet 8
WR_EN: A20.R2 A21.R2 B20.R2 ; also sheet 3,5,9,12
Unconnected: AB01.BM1 AB01.BR1

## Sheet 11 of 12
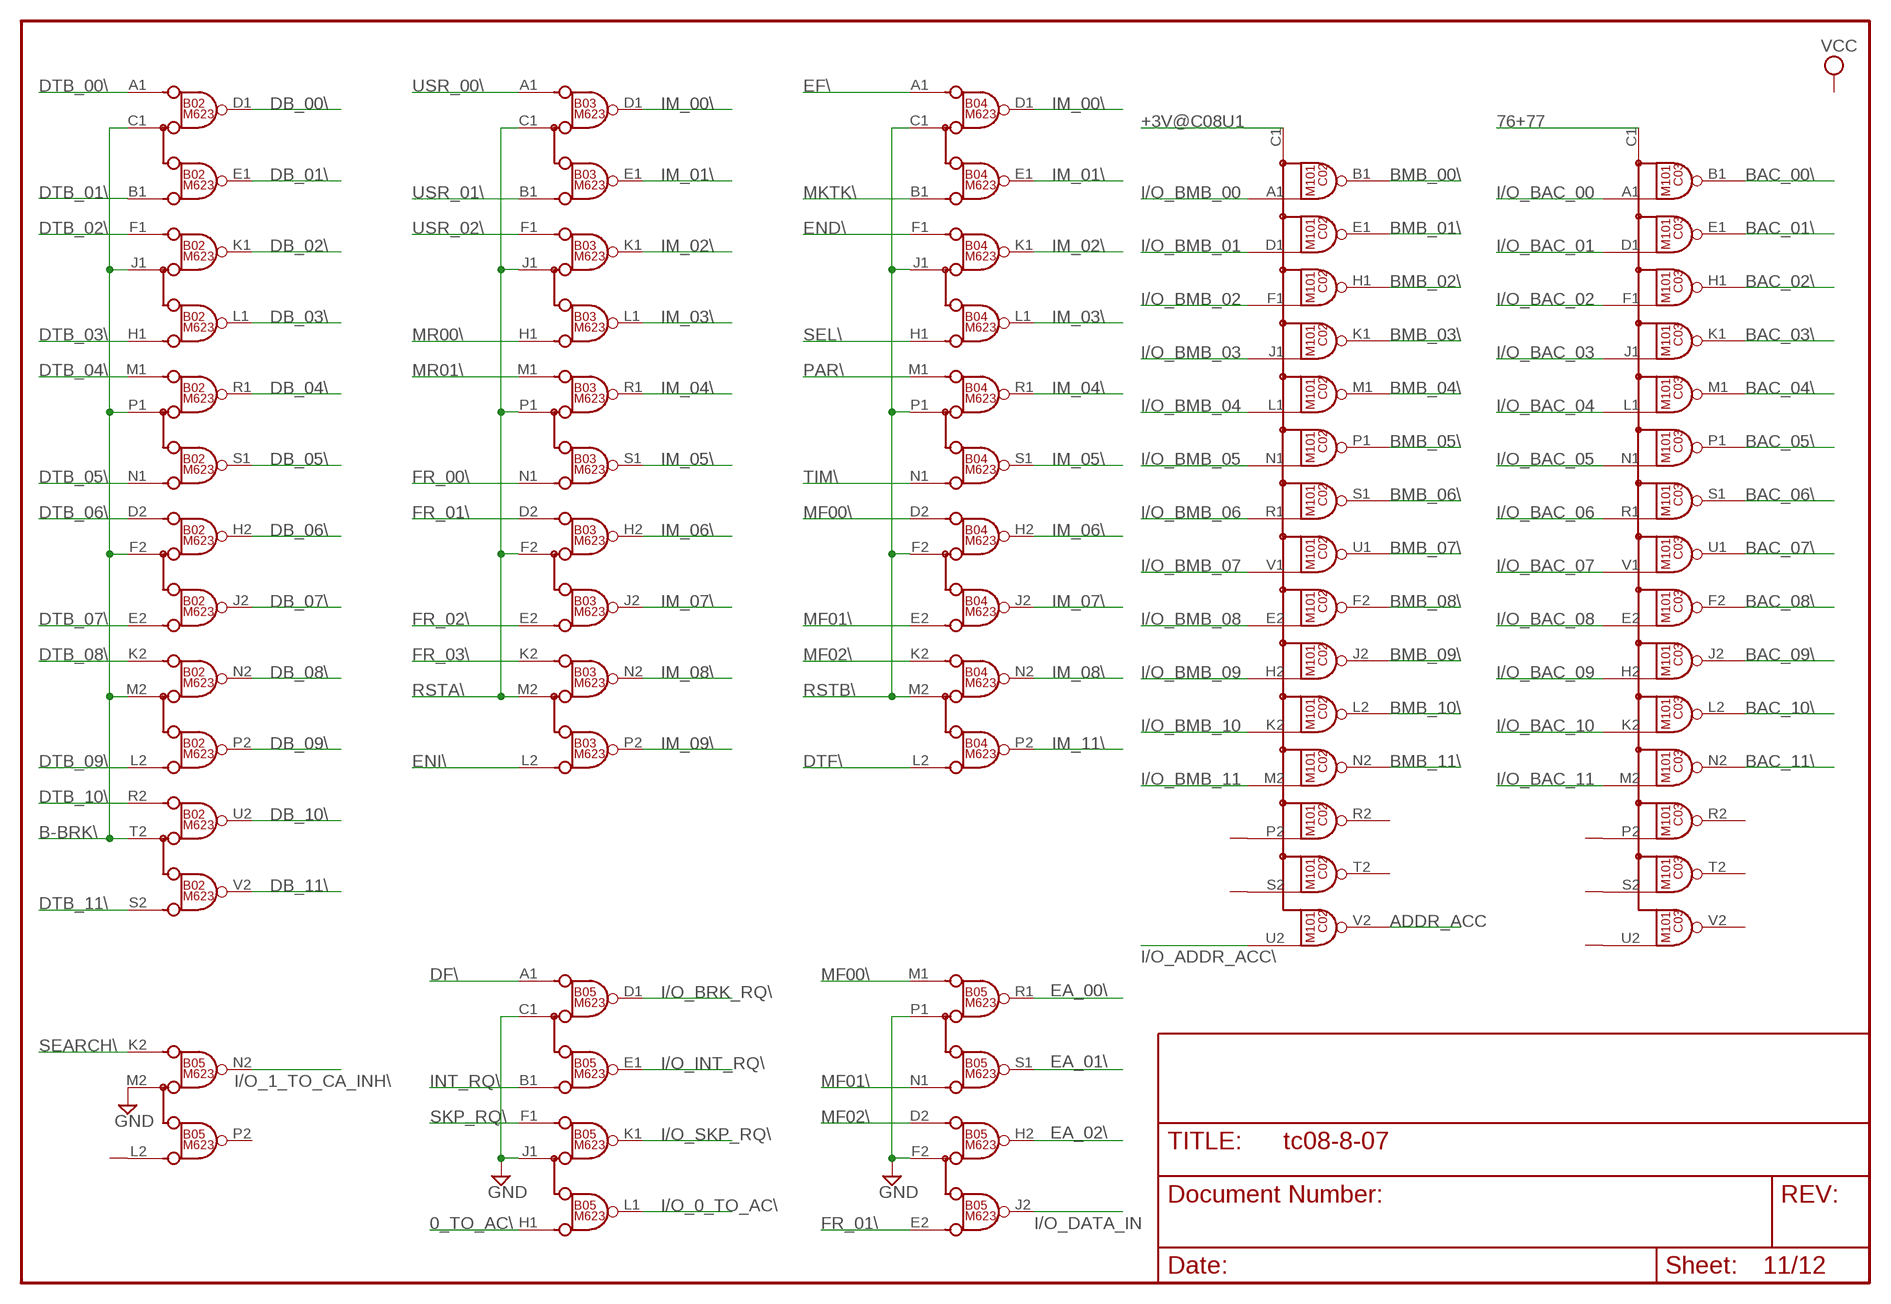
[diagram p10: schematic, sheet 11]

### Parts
B02  M623  [H807]
B03  M623  [H807]
B04  M623  [H807]
B05  M623  [H807]
C02  M101  M101-ARRAY  [H807]
C03  M101  M101-ARRAY  [H807]

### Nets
0_TO_AC\: B05.H1(B) ; also sheet 1
76+77: C03.C1(ENABLE) ; also sheet 1
+3V@C08U1: C02.C1(ENABLE) ; also sheet 1
ADDR_ACC: C02.V2(O15) ; also sheet 1
B-BRK\: B02.C1(C) B02.F2(C) B02.J1(C) B02.M2(C) B02.P1(C) B02.T2(C) ; also sheet 1
BAC_00\: C03.B1(O1) ; also sheet 3,10
BAC_01\: C03.E1(O2) ; also sheet 3,10
BAC_02\: C03.H1(O3) ; also sheet 3,10
BAC_03\: C03.K1(O4) ; also sheet 3,10
BAC_04\: C03.M1(O5) ; also sheet 3,10
BAC_05\: C03.P1(O6) ; also sheet 10
BAC_06\: C03.S1(O7) ; also sheet 10
BAC_07\: C03.U1(O8) ; also sheet 10
BAC_08\: C03.F2(O9) ; also sheet 10
BAC_09\: C03.J2(O10) ; also sheet 10
BAC_10\: C03.L2(O11) ; also sheet 6,10
BAC_11\: C03.N2(O12) ; also sheet 4,10
BMB_00\: C02.B1(O1) ; also sheet 10
BMB_01\: C02.E1(O2) ; also sheet 10
BMB_02\: C02.H1(O3) ; also sheet 10
BMB_03\: C02.K1(O4) ; also sheet 10
BMB_04\: C02.M1(O5) ; also sheet 10
BMB_05\: C02.P1(O6) ; also sheet 10
BMB_06\: C02.S1(O7) ; also sheet 10
BMB_07\: C02.U1(O8) ; also sheet 10
BMB_08\: C02.F2(O9) ; also sheet 10
BMB_09\: C02.J2(O10) ; also sheet 10
BMB_10\: C02.L2(O11) ; also sheet 10
BMB_11\: C02.N2(O12) ; also sheet 10
DB_00\: B02.D1(D) ; also sheet 12
DB_01\: B02.E1(E) ; also sheet 12
DB_02\: B02.K1(D) ; also sheet 12
DB_03\: B02.L1(E) ; also sheet 12
DB_04\: B02.R1(D) ; also sheet 12
DB_05\: B02.S1(E) ; also sheet 12
DB_06\: B02.H2(D) ; also sheet 12
DB_07\: B02.J2(E) ; also sheet 12
DB_08\: B02.N2(D) ; also sheet 12
DB_09\: B02.P2(E) ; also sheet 12
DB_10\: B02.U2(D) ; also sheet 12
DB_11\: B02.V2(E) ; also sheet 12
DF\: B05.A1(A) ; also sheet 4,5
DTB_00\: B02.A1(A) ; also sheet 8
DTB_01\: B02.B1(B) ; also sheet 8
DTB_02\: B02.F1(A) ; also sheet 8
DTB_03\: B02.H1(B) ; also sheet 8
DTB_04\: B02.M1(A) ; also sheet 8
DTB_05\: B02.N1(B) ; also sheet 8
DTB_06\: B02.D2(A) ; also sheet 8
DTB_07\: B02.E2(B) ; also sheet 8
DTB_08\: B02.K2(A) ; also sheet 8
DTB_09\: B02.L2(B) ; also sheet 8
DTB_10\: B02.R2(A) ; also sheet 8
DTB_11\: B02.S2(B) ; also sheet 8
DTF\: B04.L2(B) ; also sheet 4,5
EA_00\: B05.R1(D) ; also sheet 12
EA_01\: B05.S1(E) ; also sheet 12
EA_02\: B05.H2(D) ; also sheet 12
EF\: B04.A1(A) ; also sheet 6
END\: B04.F1(A) ; also sheet 6
ENI\: B03.L2(B) ; also sheet 2
FR_00\: B03.N1(B) ; also sheet 2,4
FR_01\: B03.D2(A) B05.E2(B) ; also sheet 2,5
FR_02\: B03.E2(B) ; also sheet 2
FR_03\: B03.K2(A) ; also sheet 2
GND [Power]: B05.C1(C) B05.F2(C) B05.J1(C) B05.M2(C) B05.P1(C) ; also sheet 1,2,4,10,12
I/O_0_TO_AC\: B05.L1(E) ; also sheet 12
I/O_1_TO_CA_INH\: B05.N2(D) ; also sheet 12
I/O_ADDR_ACC\: C02.U2(IN15) ; also sheet 12
I/O_BAC_00: C03.A1(IN1) ; also sheet 12
I/O_BAC_01: C03.D1(IN2) ; also sheet 12
I/O_BAC_02: C03.F1(IN3) ; also sheet 12
I/O_BAC_03: C03.J1(IN4) ; also sheet 12
I/O_BAC_04: C03.L1(IN5) ; also sheet 12
I/O_BAC_05: C03.N1(IN6) ; also sheet 12
I/O_BAC_06: C03.R1(IN7) ; also sheet 12
I/O_BAC_07: C03.V1(IN8) ; also sheet 12
I/O_BAC_08: C03.E2(IN9) ; also sheet 12
I/O_BAC_09: C03.H2(IN10) ; also sheet 12
I/O_BAC_10: C03.K2(IN11) ; also sheet 12
I/O_BAC_11: C03.M2(IN12) ; also sheet 12
I/O_BMB_00: C02.A1(IN1) ; also sheet 12
I/O_BMB_01: C02.D1(IN2) ; also sheet 12
I/O_BMB_02: C02.F1(IN3) ; also sheet 12
I/O_BMB_03: C02.J1(IN4) ; also sheet 1,12
I/O_BMB_04: C02.L1(IN5) ; also sheet 1,12
I/O_BMB_05: C02.N1(IN6) ; also sheet 1,12
I/O_BMB_06: C02.R1(IN7) ; also sheet 1,12
I/O_BMB_07: C02.V1(IN8) ; also sheet 1,12
I/O_BMB_08: C02.E2(IN9) ; also sheet 1,12
I/O_BMB_09: C02.H2(IN10) ; also sheet 12
I/O_BMB_10: C02.K2(IN11) ; also sheet 12
I/O_BMB_11: C02.M2(IN12) ; also sheet 12
I/O_BRK_RQ\: B05.D1(D) ; also sheet 12
I/O_DATA_IN: B05.J2(E) ; also sheet 12
I/O_INT_RQ\: B05.E1(E) ; also sheet 12
I/O_SKP_RQ\: B05.K1(D) ; also sheet 12
IM_00\: B03.D1(D) B04.D1(D) ; also sheet 12
IM_01\: B03.E1(E) B04.E1(E) ; also sheet 12
IM_02\: B03.K1(D) B04.K1(D) ; also sheet 12
IM_03\: B03.L1(E) B04.L1(E) ; also sheet 12
IM_04\: B03.R1(D) B04.R1(D) ; also sheet 12
IM_05\: B03.S1(E) B04.S1(E) ; also sheet 12
IM_06\: B03.H2(D) B04.H2(D) ; also sheet 12
IM_07\: B03.J2(E) B04.J2(E) ; also sheet 12
IM_08\: B03.N2(D) B04.N2(D) ; also sheet 12
IM_09\: B03.P2(E) ; also sheet 12
IM_11\: B04.P2(E) ; also sheet 12
INT_RQ\: B05.B1(B) ; also sheet 1
MF00\: B04.D2(A) B05.M1(A) ; also sheet 1
MF01\: B04.E2(B) B05.N1(B) ; also sheet 1
MF02\: B04.K2(A) B05.D2(A) ; also sheet 1
MKTK\: B04.B1(B) ; also sheet 6
MR00\: B03.H1(B) ; also sheet 2
MR01\: B03.M1(A) ; also sheet 2
NC: B05.L2(B) C02.P2(IN13) C02.S2(IN14) C03.P2(IN13) C03.S2(IN14) C03.U2(IN15) ; also sheet 2,3,10,12
PAR\: B04.M1(A) ; also sheet 6
RSTA\: B03.C1(C) B03.F2(C) B03.J1(C) B03.M2(C) B03.P1(C) ; also sheet 1
RSTB\: B04.C1(C) B04.F2(C) B04.J1(C) B04.M2(C) B04.P1(C) ; also sheet 1
SEARCH\: B05.K2(A) ; also sheet 2,5
SEL\: B04.H1(B) ; also sheet 6
SKP_RQ\: B05.F1(A) ; also sheet 1
TIM\: B04.N1(B) ; also sheet 6
USR_00\: B03.A1(A) ; also sheet 2
USR_01\: B03.B1(B) ; also sheet 2
USR_02\: B03.F1(A) ; also sheet 2
Unconnected: B03.R2(A) B03.S2(B) B03.T2(C) B03.U2(D) B03.V2(E) B04.R2(A) B04.S2(B) B04.T2(C) B04.U2(D) B04.V2(E) B05.P2(E) B05.R2(A) B05.S2(B) B05.T2(C) B05.U2(D) B05.V2(E) C02.R2(O13) C02.T2(O14) C03.R2(O13) C03.T2(O14) C03.V2(O15)

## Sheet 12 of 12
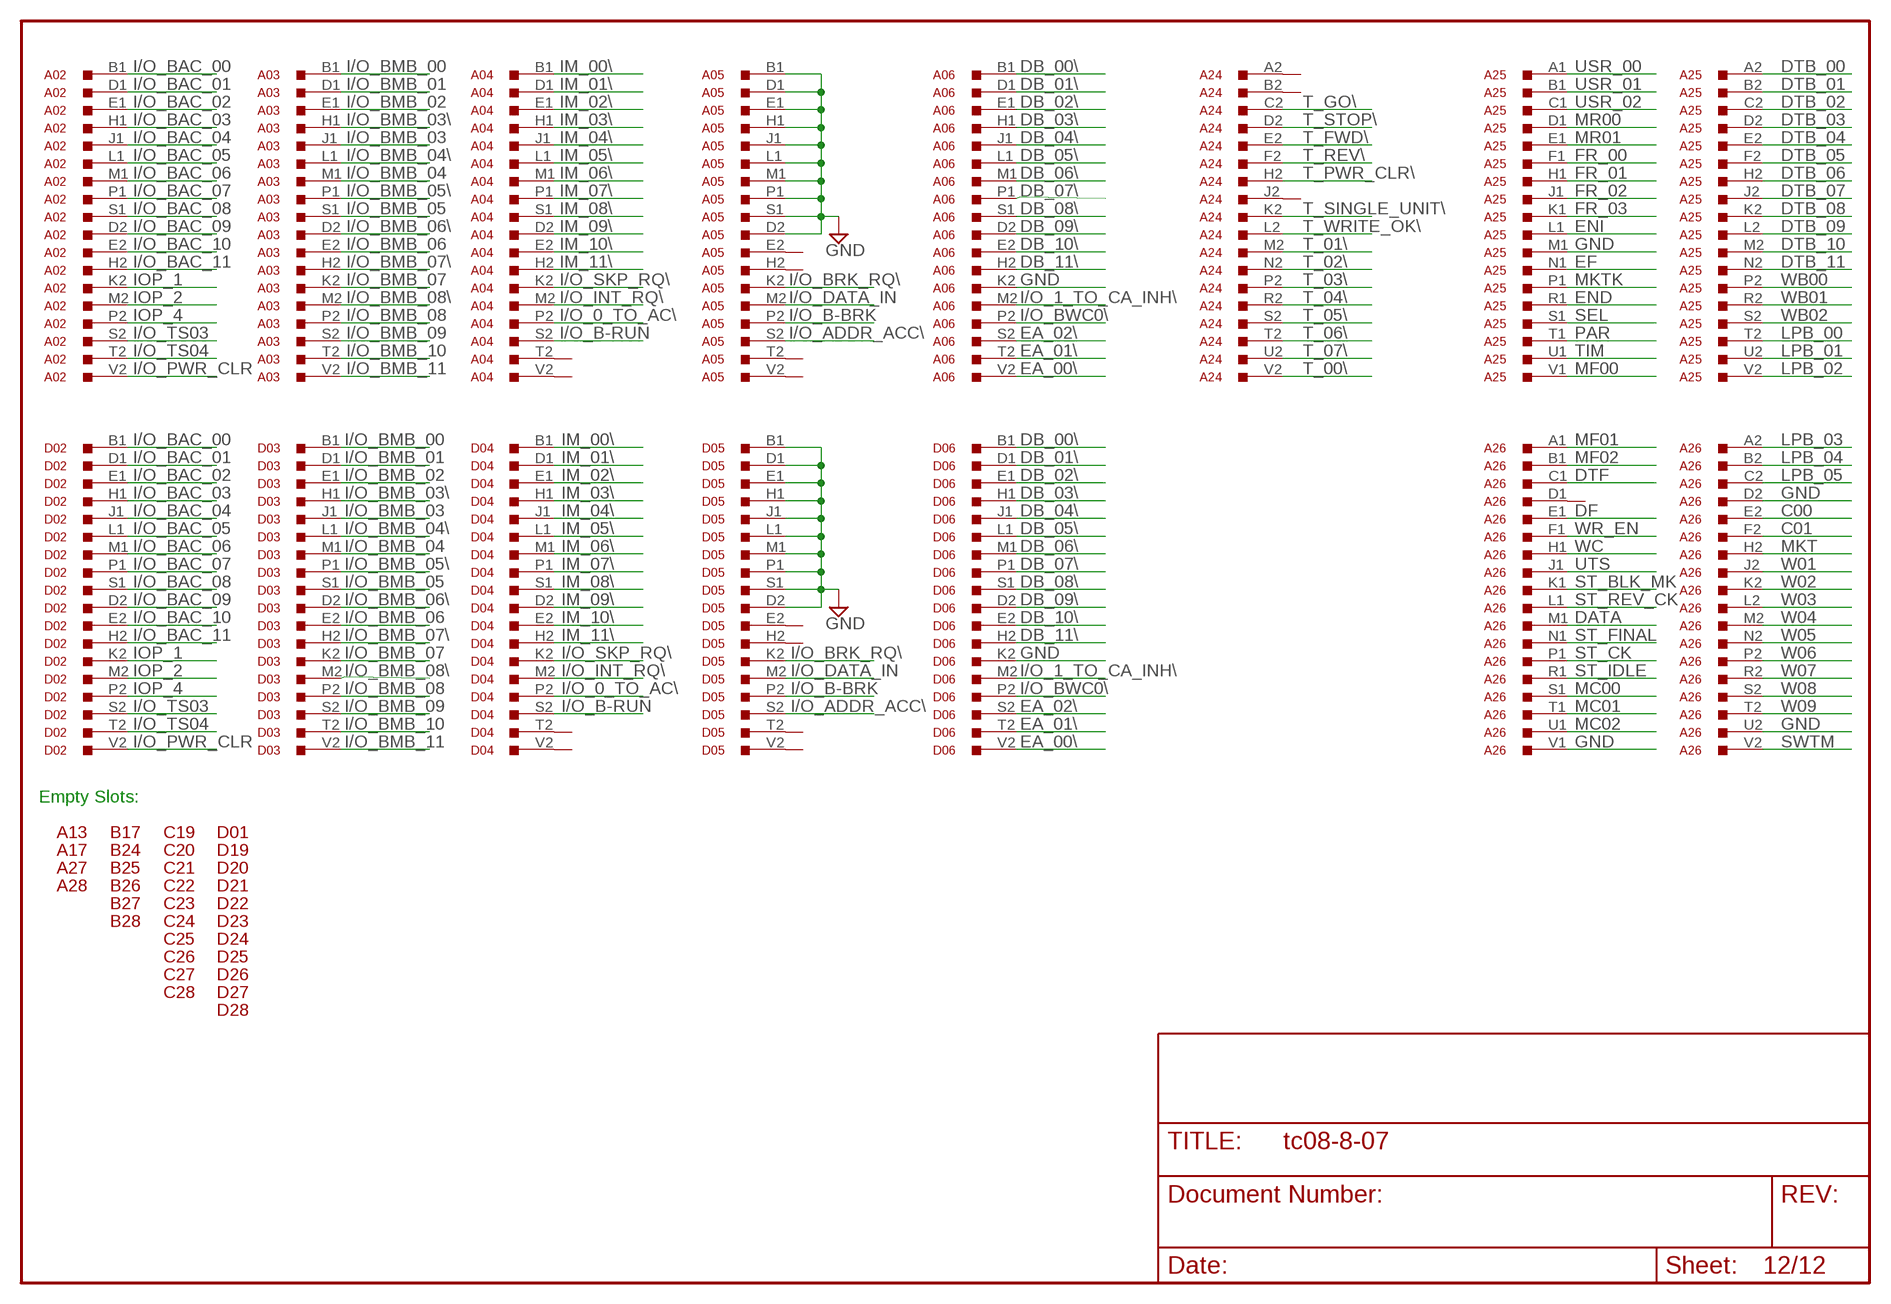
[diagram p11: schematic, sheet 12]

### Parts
A02  M903  [H807]
A03  M903  [H807]
A04  M903  [H807]
A05  M903  [H807]
A06  M903  [H807]
A13  H807  [H807]
A17  H807  [H807]
A24  W023  [H807]
A25  M916  [H807]
A26  M916  [H807]
A27  H807  [H807]
A28  H807  [H807]
B17  H807  [H807]
B24  H807  [H807]
B25  H807  [H807]
B26  H807  [H807]
B27  H807  [H807]
B28  H807  [H807]
C19  H807  [H807]
C20  H807  [H807]
C21  H807  [H807]
C22  H807  [H807]
C23  H807  [H807]
C24  H807  [H807]
C25  H807  [H807]
C26  H807  [H807]
C27  H807  [H807]
C28  H807  [H807]
D01  H807  [H807]
D02  M903  [H807]
D03  M903  [H807]
D04  M903  [H807]
D05  M903  [H807]
D06  M903  [H807]
D19  H807  [H807]
D20  H807  [H807]
D21  H807  [H807]
D22  H807  [H807]
D23  H807  [H807]
D24  H807  [H807]
D25  H807  [H807]
D26  H807  [H807]
D27  H807  [H807]
D28  H807  [H807]

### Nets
C00: A26.E2 ; also sheet 4,5,9
C01: A26.F2 ; also sheet 4,5
DATA: A26.M1 ; also sheet 5,7
DB_00\: A06.B1 D06.B1 ; also sheet 11
DB_01\: A06.D1 D06.D1 ; also sheet 11
DB_02\: A06.E1 D06.E1 ; also sheet 11
DB_03\: A06.H1 D06.H1 ; also sheet 11
DB_04\: A06.J1 D06.J1 ; also sheet 11
DB_05\: A06.L1 D06.L1 ; also sheet 11
DB_06\: A06.M1 D06.M1 ; also sheet 11
DB_07\: A06.P1 D06.P1 ; also sheet 11
DB_08\: A06.S1 D06.S1 ; also sheet 11
DB_09\: A06.D2 D06.D2 ; also sheet 11
DB_10\: A06.E2 D06.E2 ; also sheet 11
DB_11\: A06.H2 D06.H2 ; also sheet 11
DF: A26.E1 ; also sheet 4,6
DTB_00: A25.A2 ; also sheet 8,9
DTB_01: A25.B2 ; also sheet 8,9
DTB_02: A25.C2 ; also sheet 8,9
DTB_03: A25.D2 ; also sheet 8
DTB_04: A25.E2 ; also sheet 8
DTB_05: A25.F2 ; also sheet 8
DTB_06: A25.H2 ; also sheet 8
DTB_07: A25.J2 ; also sheet 8
DTB_08: A25.K2 ; also sheet 8
DTB_09: A25.L2 ; also sheet 8
DTB_10: A25.M2 ; also sheet 8
DTB_11: A25.N2 ; also sheet 8
DTF: A26.C1 ; also sheet 1,4,6
EA_00\: A06.V2 D06.V2 ; also sheet 11
EA_01\: A06.T2 D06.T2 ; also sheet 11
EA_02\: A06.S2 D06.S2 ; also sheet 11
EF: A25.N1 ; also sheet 1,6
END: A25.R1 ; also sheet 6
ENI: A25.L1 ; also sheet 1,2
FR_00: A25.F1 ; also sheet 2,4
FR_01: A25.H1 ; also sheet 1,2,5,6
FR_02: A25.J1 ; also sheet 2
FR_03: A25.K1 ; also sheet 2,5
GND [Power]: A05.B1 A05.D1 A05.D2 A05.E1 A05.H1 A05.J1 A05.L1 A05.M1 A05.P1 A05.S1 A06.K2 A25.M1 A26.D2 A26.U2 A26.V1 D05.B1 D05.D1 D05.D2 D05.E1 D05.H1 D05.J1 D05.L1 D05.M1 D05.P1 D05.S1 D06.K2 ; also sheet 1,2,4,10,11
I/O_0_TO_AC\: A04.P2 D04.P2 ; also sheet 11
I/O_1_TO_CA_INH\: A06.M2 D06.M2 ; also sheet 11
I/O_ADDR_ACC\: A05.S2 D05.S2 ; also sheet 11
I/O_B-BRK: A05.P2 D05.P2 ; also sheet 1
I/O_B-RUN: A04.S2 D04.S2 ; also sheet 1
I/O_BAC_00: A02.B1 D02.B1 ; also sheet 11
I/O_BAC_01: A02.D1 D02.D1 ; also sheet 11
I/O_BAC_02: A02.E1 D02.E1 ; also sheet 11
I/O_BAC_03: A02.H1 D02.H1 ; also sheet 11
I/O_BAC_04: A02.J1 D02.J1 ; also sheet 11
I/O_BAC_05: A02.L1 D02.L1 ; also sheet 11
I/O_BAC_06: A02.M1 D02.M1 ; also sheet 11
I/O_BAC_07: A02.P1 D02.P1 ; also sheet 11
I/O_BAC_08: A02.S1 D02.S1 ; also sheet 11
I/O_BAC_09: A02.D2 D02.D2 ; also sheet 11
I/O_BAC_10: A02.E2 D02.E2 ; also sheet 11
I/O_BAC_11: A02.H2 D02.H2 ; also sheet 11
I/O_BMB_00: A03.B1 D03.B1 ; also sheet 11
I/O_BMB_01: A03.D1 D03.D1 ; also sheet 11
I/O_BMB_02: A03.E1 D03.E1 ; also sheet 11
I/O_BMB_03: A03.J1 D03.J1 ; also sheet 1,11
I/O_BMB_03\: A03.H1 D03.H1
I/O_BMB_04: A03.M1 D03.M1 ; also sheet 1,11
I/O_BMB_04\: A03.L1 D03.L1
I/O_BMB_05: A03.S1 D03.S1 ; also sheet 1,11
I/O_BMB_05\: A03.P1 D03.P1
I/O_BMB_06: A03.E2 D03.E2 ; also sheet 1,11
I/O_BMB_06\: A03.D2 D03.D2
I/O_BMB_07: A03.K2 D03.K2 ; also sheet 1,11
I/O_BMB_07\: A03.H2 D03.H2
I/O_BMB_08: A03.P2 D03.P2 ; also sheet 1,11
I/O_BMB_08\: A03.M2 D03.M2 ; also sheet 1
I/O_BMB_09: A03.S2 D03.S2 ; also sheet 11
I/O_BMB_10: A03.T2 D03.T2 ; also sheet 11
I/O_BMB_11: A03.V2 D03.V2 ; also sheet 11
I/O_BRK_RQ\: A05.K2 D05.K2 ; also sheet 11
I/O_BWC0\: A06.P2 D06.P2 ; also sheet 1
I/O_DATA_IN: A05.M2 D05.M2 ; also sheet 11
I/O_INT_RQ\: A04.M2 D04.M2 ; also sheet 11
I/O_PWR_CLR: A02.V2 D02.V2 ; also sheet 1
I/O_SKP_RQ\: A04.K2 D04.K2 ; also sheet 11
I/O_TS03: A02.S2 D02.S2 ; also sheet 1
I/O_TS04: A02.T2 D02.T2
IM_00\: A04.B1 D04.B1 ; also sheet 11
IM_01\: A04.D1 D04.D1 ; also sheet 11
IM_02\: A04.E1 D04.E1 ; also sheet 11
IM_03\: A04.H1 D04.H1 ; also sheet 11
IM_04\: A04.J1 D04.J1 ; also sheet 11
IM_05\: A04.L1 D04.L1 ; also sheet 11
IM_06\: A04.M1 D04.M1 ; also sheet 11
IM_07\: A04.P1 D04.P1 ; also sheet 11
IM_08\: A04.S1 D04.S1 ; also sheet 11
IM_09\: A04.D2 D04.D2 ; also sheet 11
IM_10\: A04.E2 D04.E2
IM_11\: A04.H2 D04.H2 ; also sheet 11
IOP_1: A02.K2 D02.K2 ; also sheet 1
IOP_2: A02.M2 D02.M2 ; also sheet 1
IOP_4: A02.P2 D02.P2 ; also sheet 1
LPB_00: A25.T2 ; also sheet 8,9
LPB_01: A25.U2 ; also sheet 8,9
LPB_02: A25.V2 ; also sheet 8,9
LPB_03: A26.A2 ; also sheet 8,9
LPB_04: A26.B2 ; also sheet 8,9
LPB_05: A26.C2 ; also sheet 8,9
MC00: A26.S1 ; also sheet 4
MC01: A26.T1 ; also sheet 4,6
MC02: A26.U1 ; also sheet 4,5,9
MF00: A25.V1 ; also sheet 1
MF01: A26.A1 ; also sheet 1
MF02: A26.B1 ; also sheet 1
MKT: A26.H2 ; also sheet 4,5,9
MKTK: A25.P1 ; also sheet 6
MR00: A25.D1 ; also sheet 2
MR01: A25.E1 ; also sheet 2,3
NC: A04.T2 A04.V2 A05.E2 A05.H2 A05.T2 A05.V2 A24.A2 A24.B2 A24.J2 A26.D1 D04.T2 D04.V2 D05.E2 D05.H2 D05.T2 D05.V2 ; also sheet 2,3,10,11
PAR: A25.T1 ; also sheet 6
SEL: A25.S1 ; also sheet 6
ST_BLK_MK: A26.K1 ; also sheet 5,7
ST_CK: A26.P1 ; also sheet 4,5,6,7
ST_FINAL: A26.N1 ; also sheet 4,5,7,9
ST_IDLE: A26.R1 ; also sheet 5,7
ST_REV_CK: A26.L1 ; also sheet 4,5,7,9
SWTM: A26.V2 ; also sheet 3,5,6
T_00\: A24.V2 ; also sheet 2
T_01\: A24.M2 ; also sheet 2
T_02\: A24.N2 ; also sheet 2
T_03\: A24.P2 ; also sheet 2
T_04\: A24.R2 ; also sheet 2
T_05\: A24.S2 ; also sheet 2
T_06\: A24.T2 ; also sheet 2
T_07\: A24.U2 ; also sheet 2
T_FWD\: A24.E2 ; also sheet 2
T_GO\: A24.C2 ; also sheet 2
T_PWR_CLR\: A24.H2 ; also sheet 2
T_REV\: A24.F2 ; also sheet 2
T_SINGLE_UNIT\: A24.K2 ; also sheet 6
T_STOP\: A24.D2 ; also sheet 2
T_WRITE_OK\: A24.L2 ; also sheet 2
TIM: A25.U1 ; also sheet 6
USR_00: A25.A1 ; also sheet 2
USR_01: A25.B1 ; also sheet 2
USR_02: A25.C1 ; also sheet 2
UTS: A26.J1 ; also sheet 3,5
W01: A26.J2 ; also sheet 7
W02: A26.K2 ; also sheet 7
W03: A26.L2 ; also sheet 7
W04: A26.M2 ; also sheet 7
W05: A26.N2 ; also sheet 7
W06: A26.P2 ; also sheet 7
W07: A26.R2 ; also sheet 7
W08: A26.S2 ; also sheet 7
W09: A26.T2 ; also sheet 7
WB00: A25.P2 ; also sheet 8,9,10
WB01: A25.R2 ; also sheet 8,9,10
WB02: A25.S2 ; also sheet 8,9,10
WC: A26.H1 ; also sheet 1,4,5
WR_EN: A26.F1 ; also sheet 3,5,9,10

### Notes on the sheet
- Empty Slots:

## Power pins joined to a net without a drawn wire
-15V: A18.B2(-15V) A20.B2(-15V) A21.B2(-15V) A22.B2(-15V) A23.B2(-15V) B18.B2(-15V) B20.B2(-15V) B21.B2(-15V) B22.B2(-15V) B23.B2 D14.B2(-15V)
GND: A02.A1 A02.C1 A02.C2 A02.F1 A02.F2 A02.J2 A02.K1 A02.L2 A02.N1 A02.N2 A02.R1 A02.R2 A02.T1 A02.U2 A03.A1 A03.C1 A03.C2 A03.F1 A03.F2 A03.J2 A03.K1 A03.L2 A03.N1 A03.N2 A03.R1 A03.R2 A03.T1 A03.U2 A04.A1 A04.C1 A04.C2 A04.F1 A04.F2 A04.J2 A04.K1 A04.L2 A04.N1 A04.N2 A04.R1 A04.R2 A04.T1 A04.U2 A05.A1 A05.C1 A05.C2 A05.F1 A05.F2 A05.J2 A05.K1 A05.L2 A05.N1 A05.N2 A05.R1 A05.R2 A05.T1 A05.U2 A06.A1 A06.C1 A06.C2 A06.F1 A06.F2 A06.J2 A06.K1 A06.L2 A06.N1 A06.N2 A06.R1 A06.R2 A06.T1 A06.U2 A07.C2(GND) A07.T1(GND) A08.C2(GND) A08.T1(GND) A09.C2(GND) A09.T1(GND) A10.C2(GND) A10.T1(GND) A11.C2(GND) A11.T1(GND) A12.C2(GND) A12.T1(GND) A14.C2(GND) A14.T1(GND) A15.C2(GND) A15.T1(GND) A16.C2(GND) A16.T1(GND) A18.C2(GND) A20.C2(GND) A21.C2(GND) A22.C2(GND) A22.M2(GND) A23.C2(GND) A23.T1(GND) A23.U1(GND) A23.V1(GND) AB19.AC2 AB19.AK2 AB19.AS2 AB19.AT2 AB19.BE2 AB19.BL2 B02.C2(GND) B02.T1(GND) B02.U1(GND) B02.V1(GND) B03.C2(GND) B03.T1(GND) B03.U1(GND) B03.V1(GND) B04.C2(GND) B04.T1(GND) B04.U1(GND) B04.V1(GND) B05.C2(GND) B05.T1(GND) B05.U1(GND) B05.V1(GND) B06.C2(GND) B06.T1(GND) B07.C2(GND) B07.T1(GND) B08.C2(GND) B08.T1(GND) B09.C2(GND) B09.T1(GND) B10.C2(GND) B10.T1(GND) B11.C2(GND) B11.T1(GND) B12.C2(GND) B12.T1(GND) B13.C2(GND) B13.T1(GND) B14.C2(GND) B14.T1(GND) B15.C2(GND) B15.T1(GND) B16.C2(GND) B16.T1(GND) B18.C2(GND) B20.C2(GND) B21.C2(GND) B22.C2(GND) B22.T1(GND) B22.U1(GND) B22.V1(GND) B23.C2 C01.C2(GND) C01.T1(GND) C02.C2(GND) C02.T1(GND) C03.C2(GND) C03.T1(GND) C04.C2(GND) C04.T1(GND) C05.C2(GND) C05.T1(GND) C06.C2(GND) C06.T1(GND) C07.C2(GND) C07.T1(GND) C08.C2(GND) C08.T1(GND) C09.C2(GND) C09.T1(GND) C10.C2(GND) C10.T1(GND) C11.C2(GND) C11.T1(GND) C12.C2(GND) C12.T1(GND) C13.C2(GND) C13.T1(GND) C14.C2(GND) C14.T1(GND) C15.C2(GND) C15.T1(GND) C16.C2(GND) C16.T1(GND) C17.C2(GND) C17.T1(GND) CD18.AC2(GND) CD18.AT1(GND) CD18.BC2(GND) CD18.BT1(GND) D02.A1 D02.C1 D02.C2 D02.F1 D02.F2 D02.J2 D02.K1 D02.L2 D02.N1 D02.N2 D02.R1 D02.R2 D02.T1 D02.U2 D03.A1 D03.C1 D03.C2 D03.F1 D03.F2 D03.J2 D03.K1 D03.L2 D03.N1 D03.N2 D03.R1 D03.R2 D03.T1 D03.U2 D04.A1 D04.C1 D04.C2 D04.F1 D04.F2 D04.J2 D04.K1 D04.L2 D04.N1 D04.N2 D04.R1 D04.R2 D04.T1 D04.U2 D05.A1 D05.C1 D05.C2 D05.F1 D05.F2 D05.J2 D05.K1 D05.L2 D05.N1 D05.N2 D05.R1 D05.R2 D05.T1 D05.U2 D06.A1 D06.C1 D06.C2 D06.F1 D06.F2 D06.J2 D06.K1 D06.L2 D06.N1 D06.N2 D06.R1 D06.R2 D06.T1 D06.U2 D07.C2(GND) D07.T1(GND) D08.C2(GND) D08.T1(GND) D09.C2(GND) D09.T1(GND) D10.C2(GND) D10.T1(GND) D11.C2(GND) D11.T1(GND) D12.C2(GND) D12.T1(GND) D13.C2(GND) D13.T1(GND) D14.C2(GND) D14.T1(GND) D15.C2(GND) D15.T1(GND) D16.C2(GND) D16.T1(GND) D17.C2(GND) D17.T1(GND)
VCC: A07.A2(VCC) A08.A2(VCC) A09.A2(VCC) A10.A2(VCC) A11.A2(VCC) A12.A2(VCC) A14.A2(VCC) A15.A2(VCC) A16.A2(VCC) A18.A2(VCC) A20.A2(VCC) A21.A2(VCC) A22.A2(VCC) A23.A2(VCC) B02.A2(VCC) B03.A2(VCC) B04.A2(VCC) B05.A2(VCC) B06.A2(VCC) B07.A2(VCC) B08.A2(VCC) B09.A2(VCC) B10.A2(VCC) B11.A2(VCC) B12.A2(VCC) B13.A2(VCC) B14.A2(VCC) B15.A2(VCC) B16.A2(VCC) B18.A2(VCC) B20.A2(VCC) B21.A2(VCC) B22.A2(VCC) C01.A2(VCC) C02.A2(VCC) C03.A2(VCC) C04.A2(VCC) C05.A2(VCC) C06.A2(VCC) C07.A2(VCC) C08.A2(VCC) C09.A2(VCC) C10.A2(VCC) C11.A2(VCC) C12.A2(VCC) C13.A2(VCC) C14.A2(VCC) C15.A2(VCC) C16.A2(VCC) C17.A2(VCC) CD18.AA2(VCC) CD18.BA2(VCC) D07.A2(VCC) D08.A2(VCC) D09.A2(VCC) D10.A2(VCC) D11.A2(VCC) D12.A2(VCC) D13.A2(VCC) D14.A2(VCC) D15.A2(VCC) D16.A2(VCC) D17.A2(VCC)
